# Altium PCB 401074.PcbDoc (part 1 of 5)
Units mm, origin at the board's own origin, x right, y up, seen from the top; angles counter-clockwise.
Board outline 70.15 x 35.15 mm, 6 copper layers (Top Layer, Mid-Layer1, Mid-Layer2, Mid-Layer3, Mid-Layer4, Bottom Layer), stack 1.549 mm thick; 239 components, 182 nets, 1034 pads, 1263 vias.
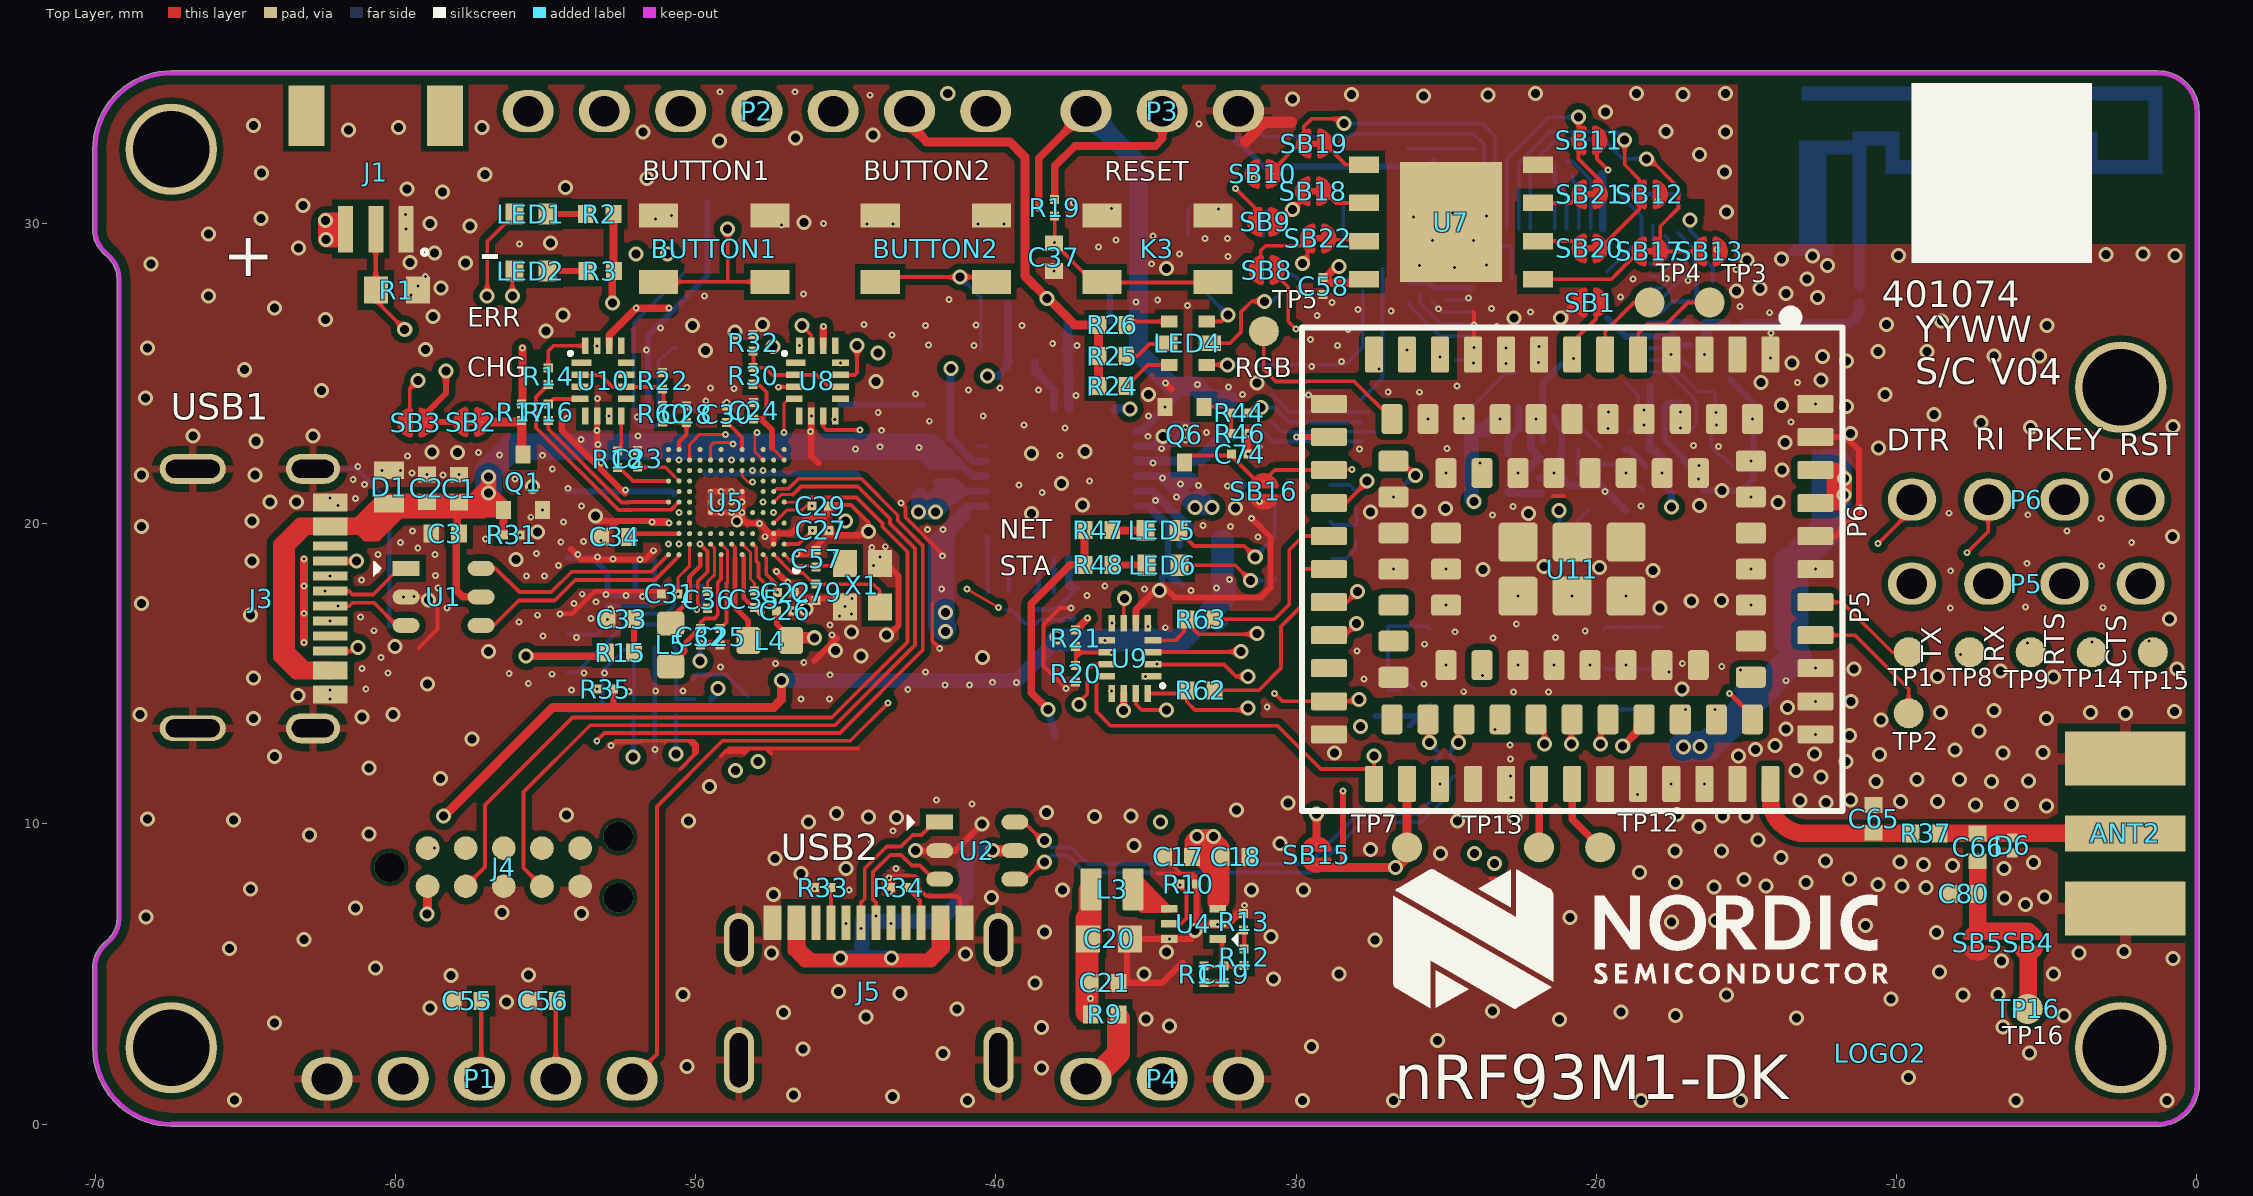
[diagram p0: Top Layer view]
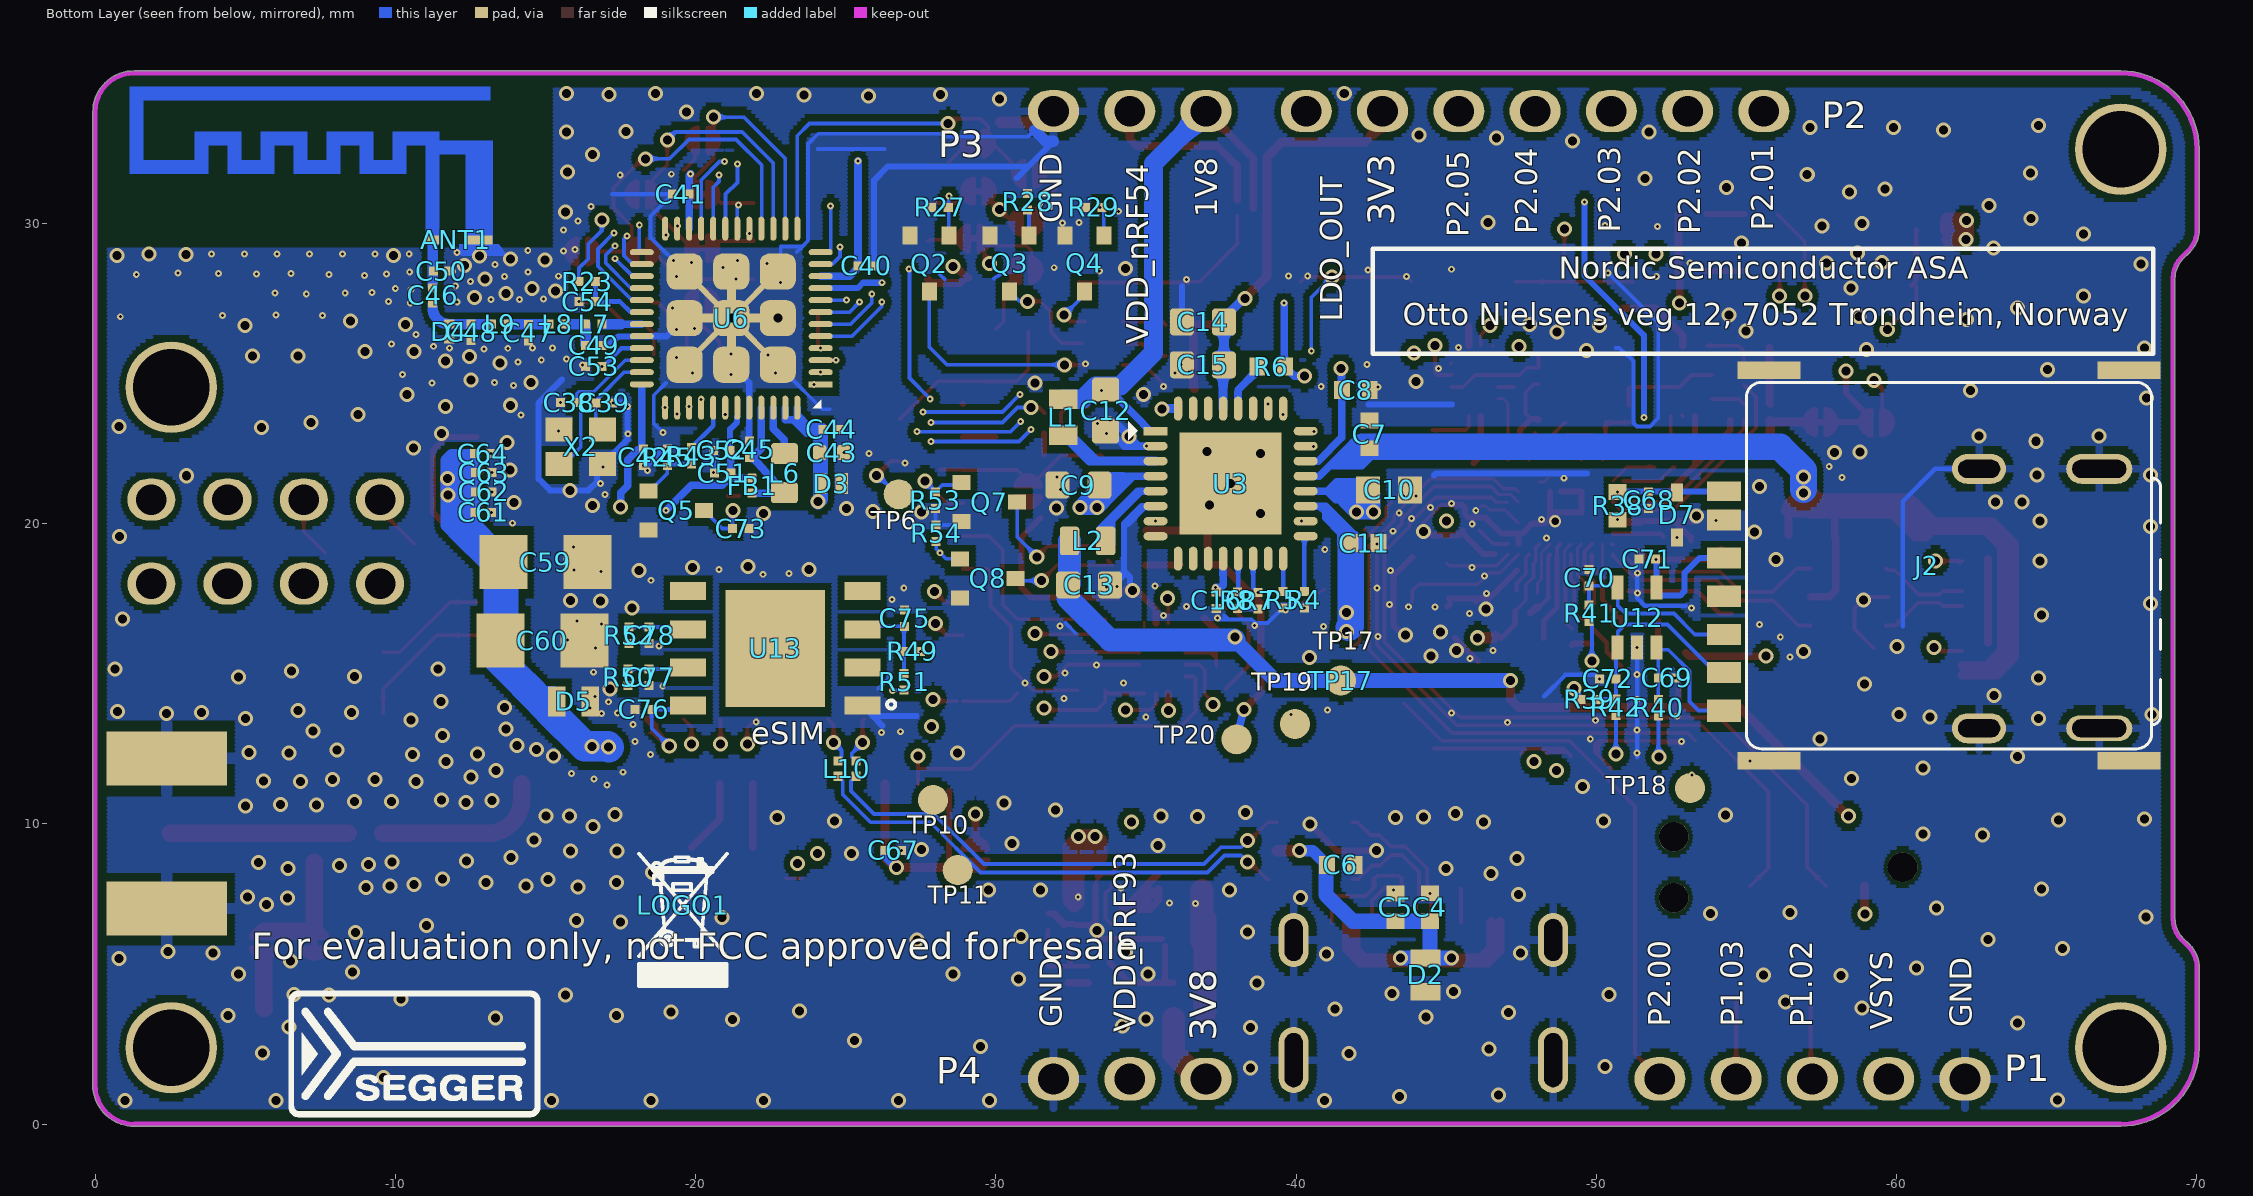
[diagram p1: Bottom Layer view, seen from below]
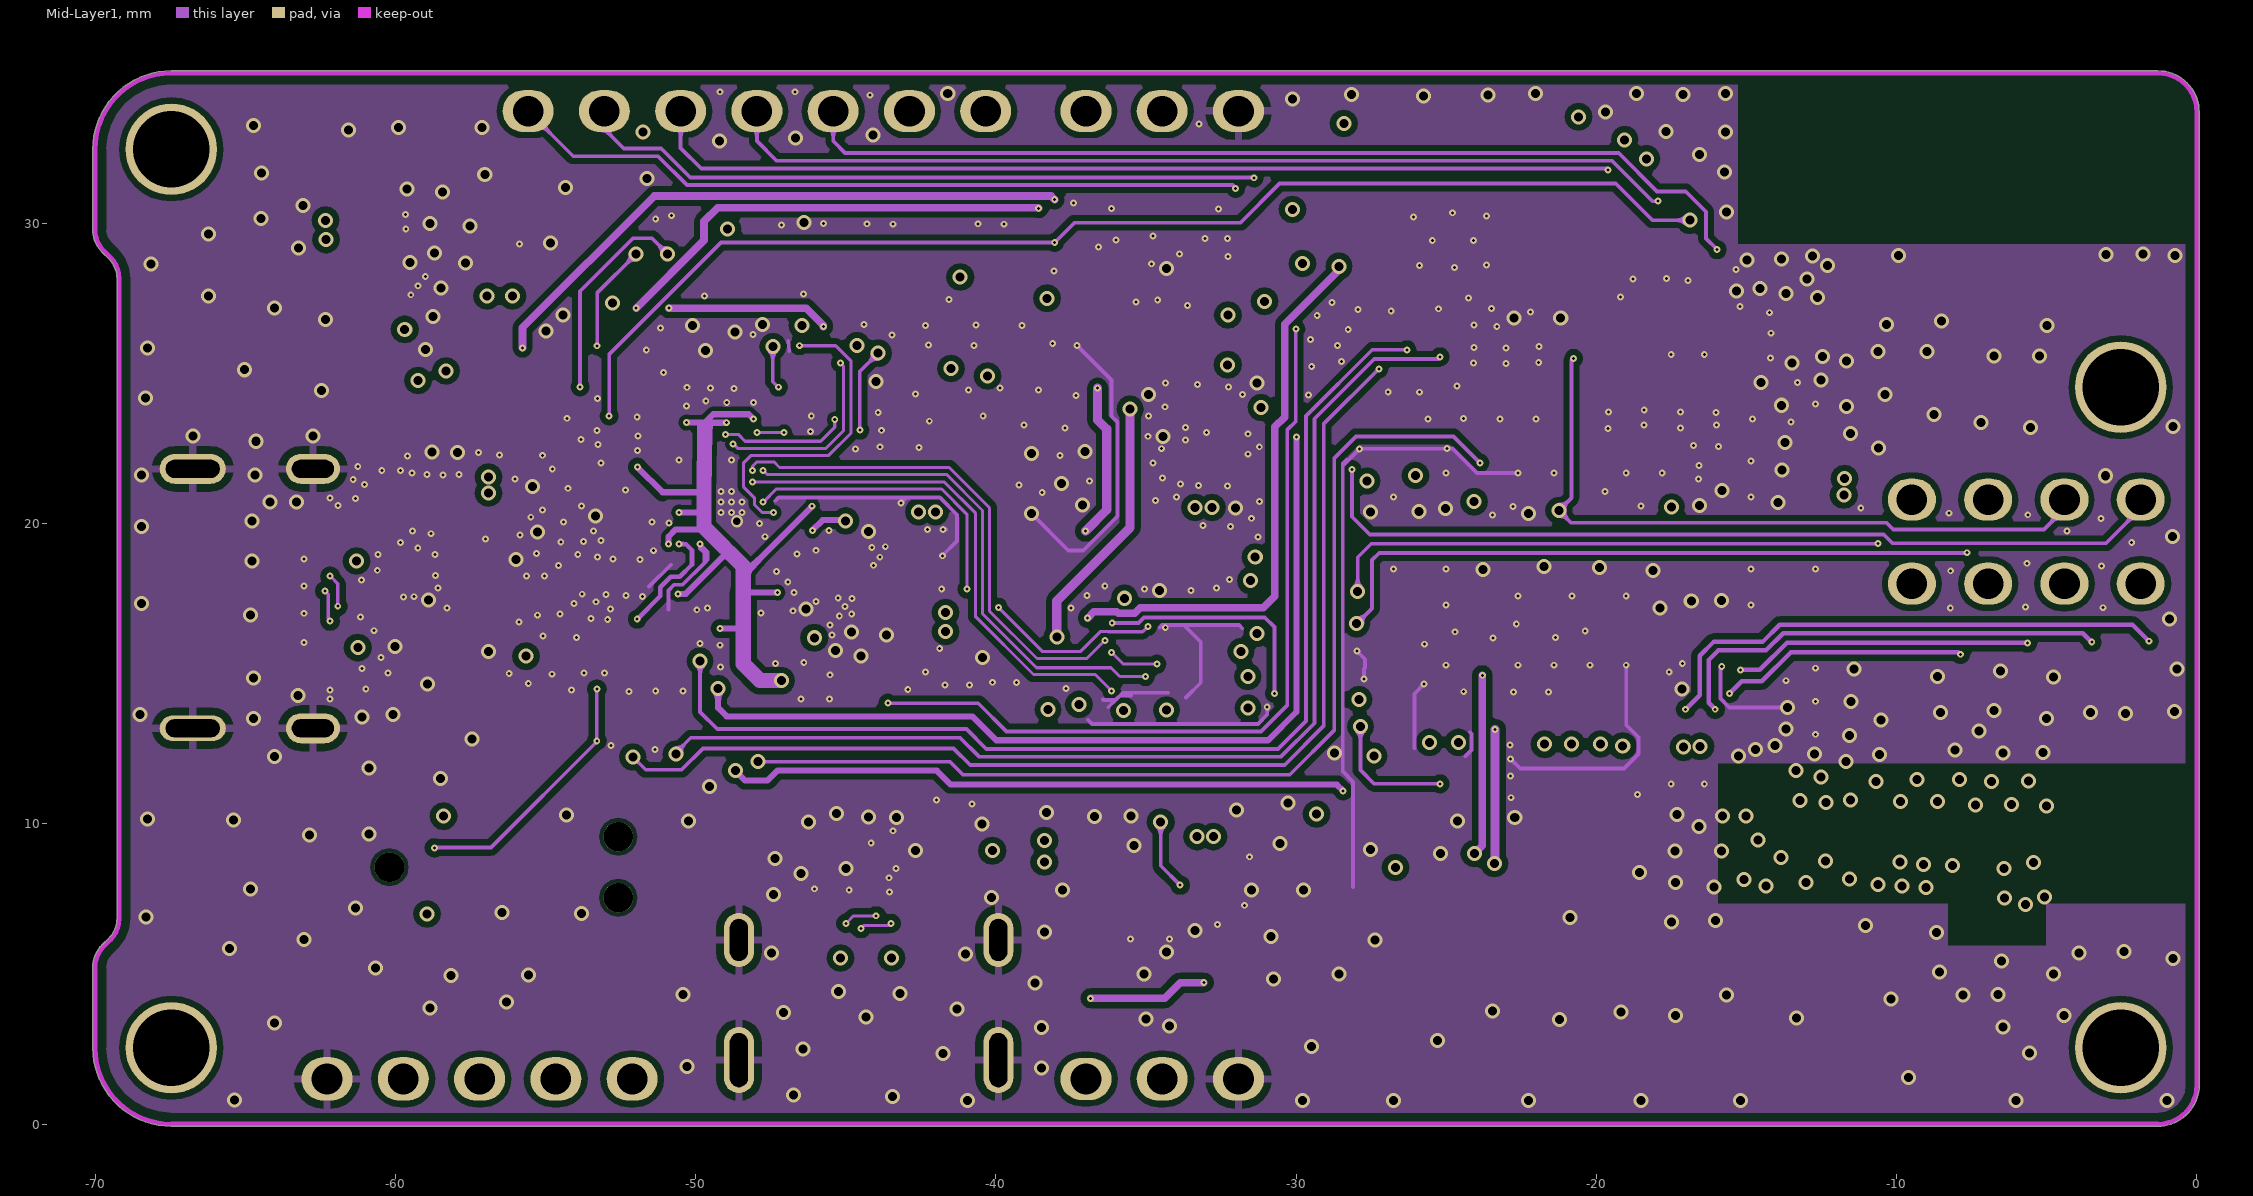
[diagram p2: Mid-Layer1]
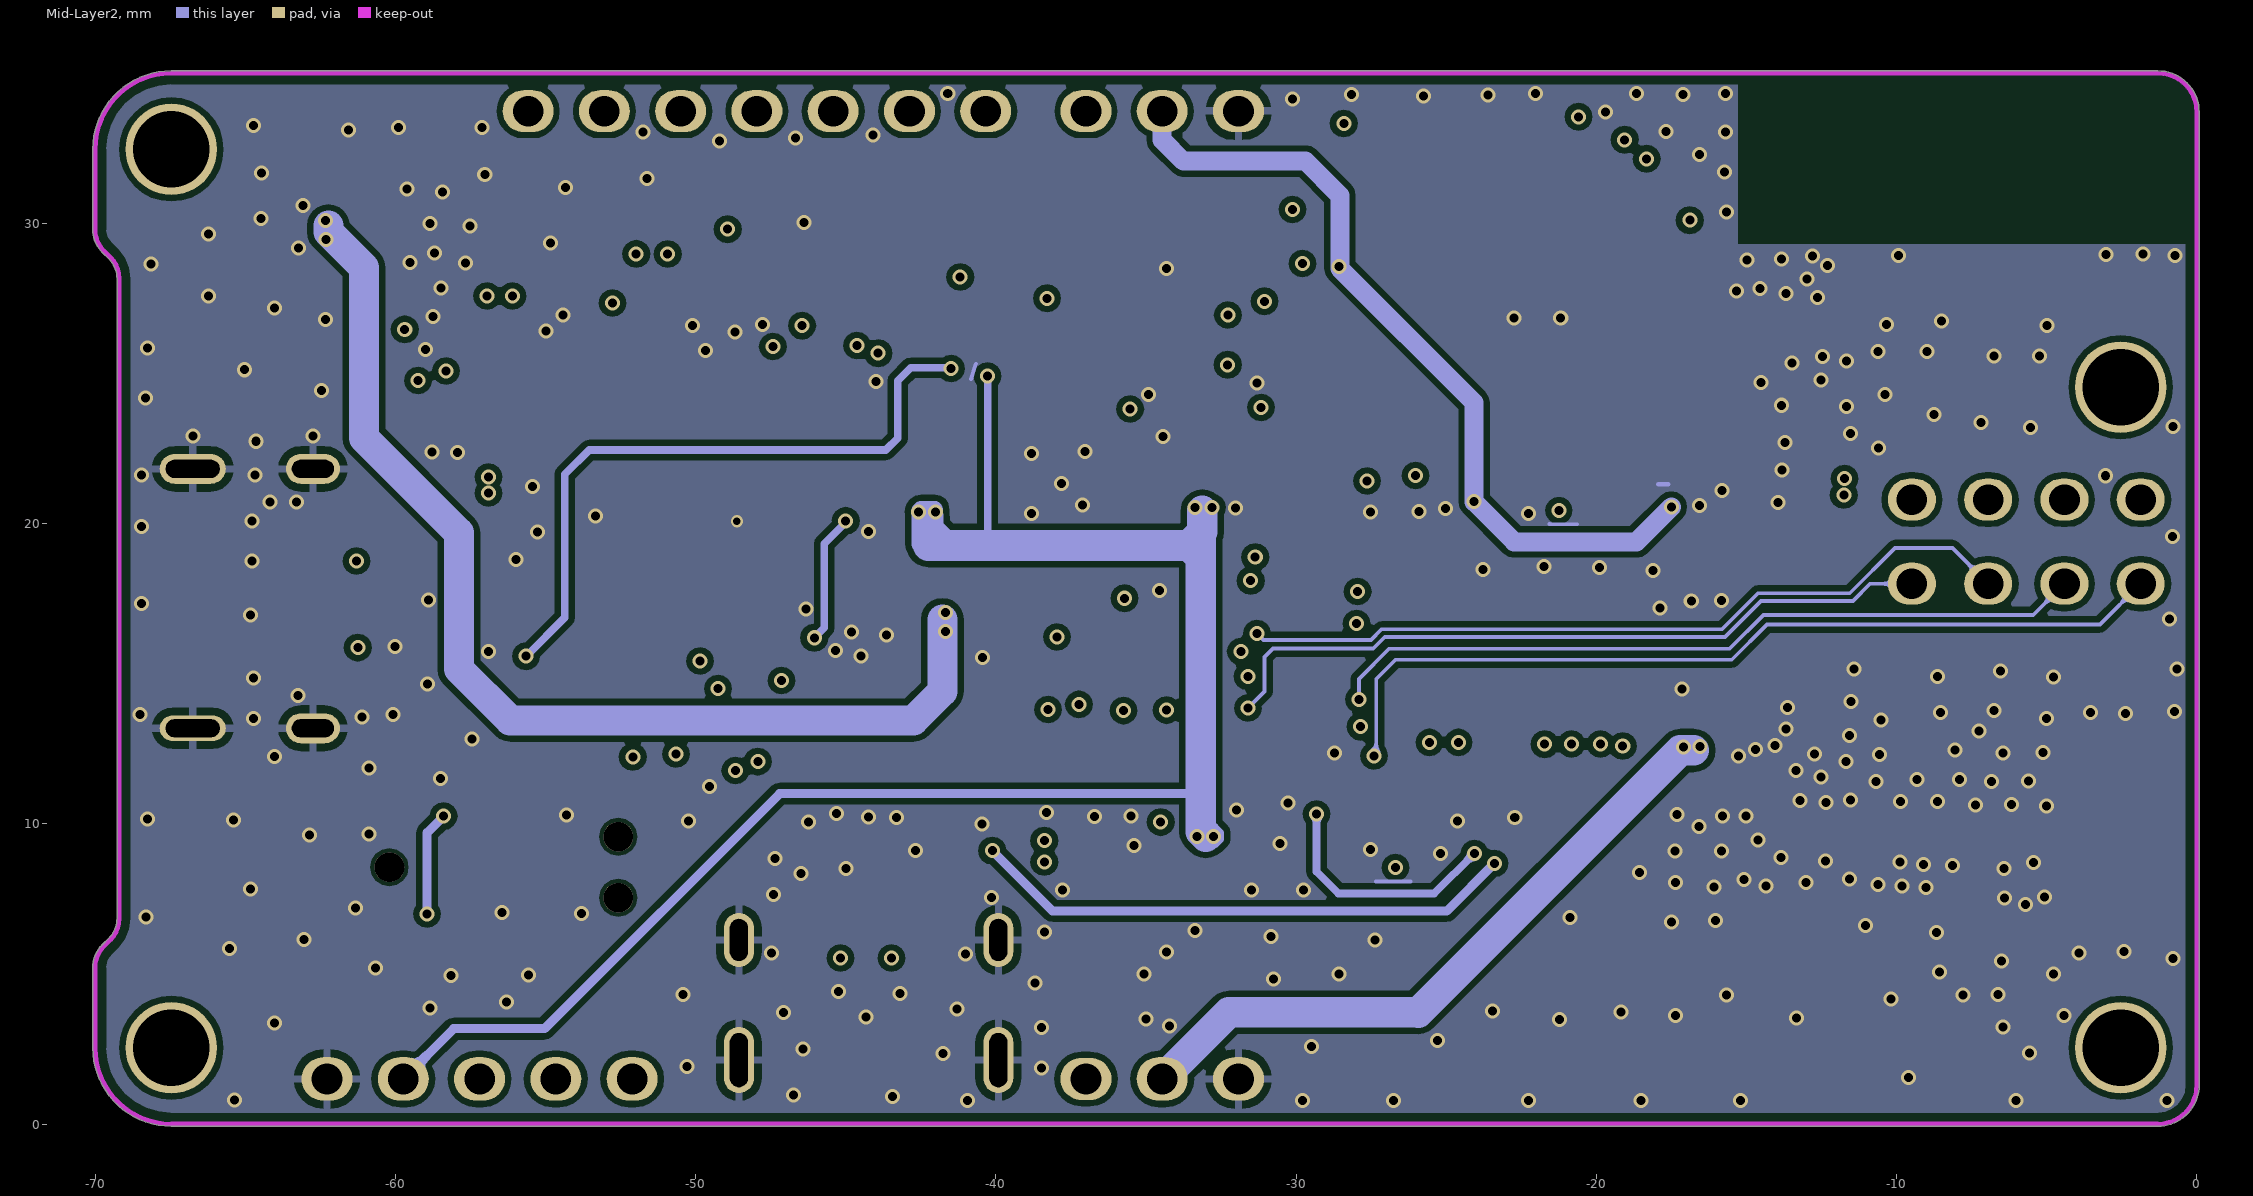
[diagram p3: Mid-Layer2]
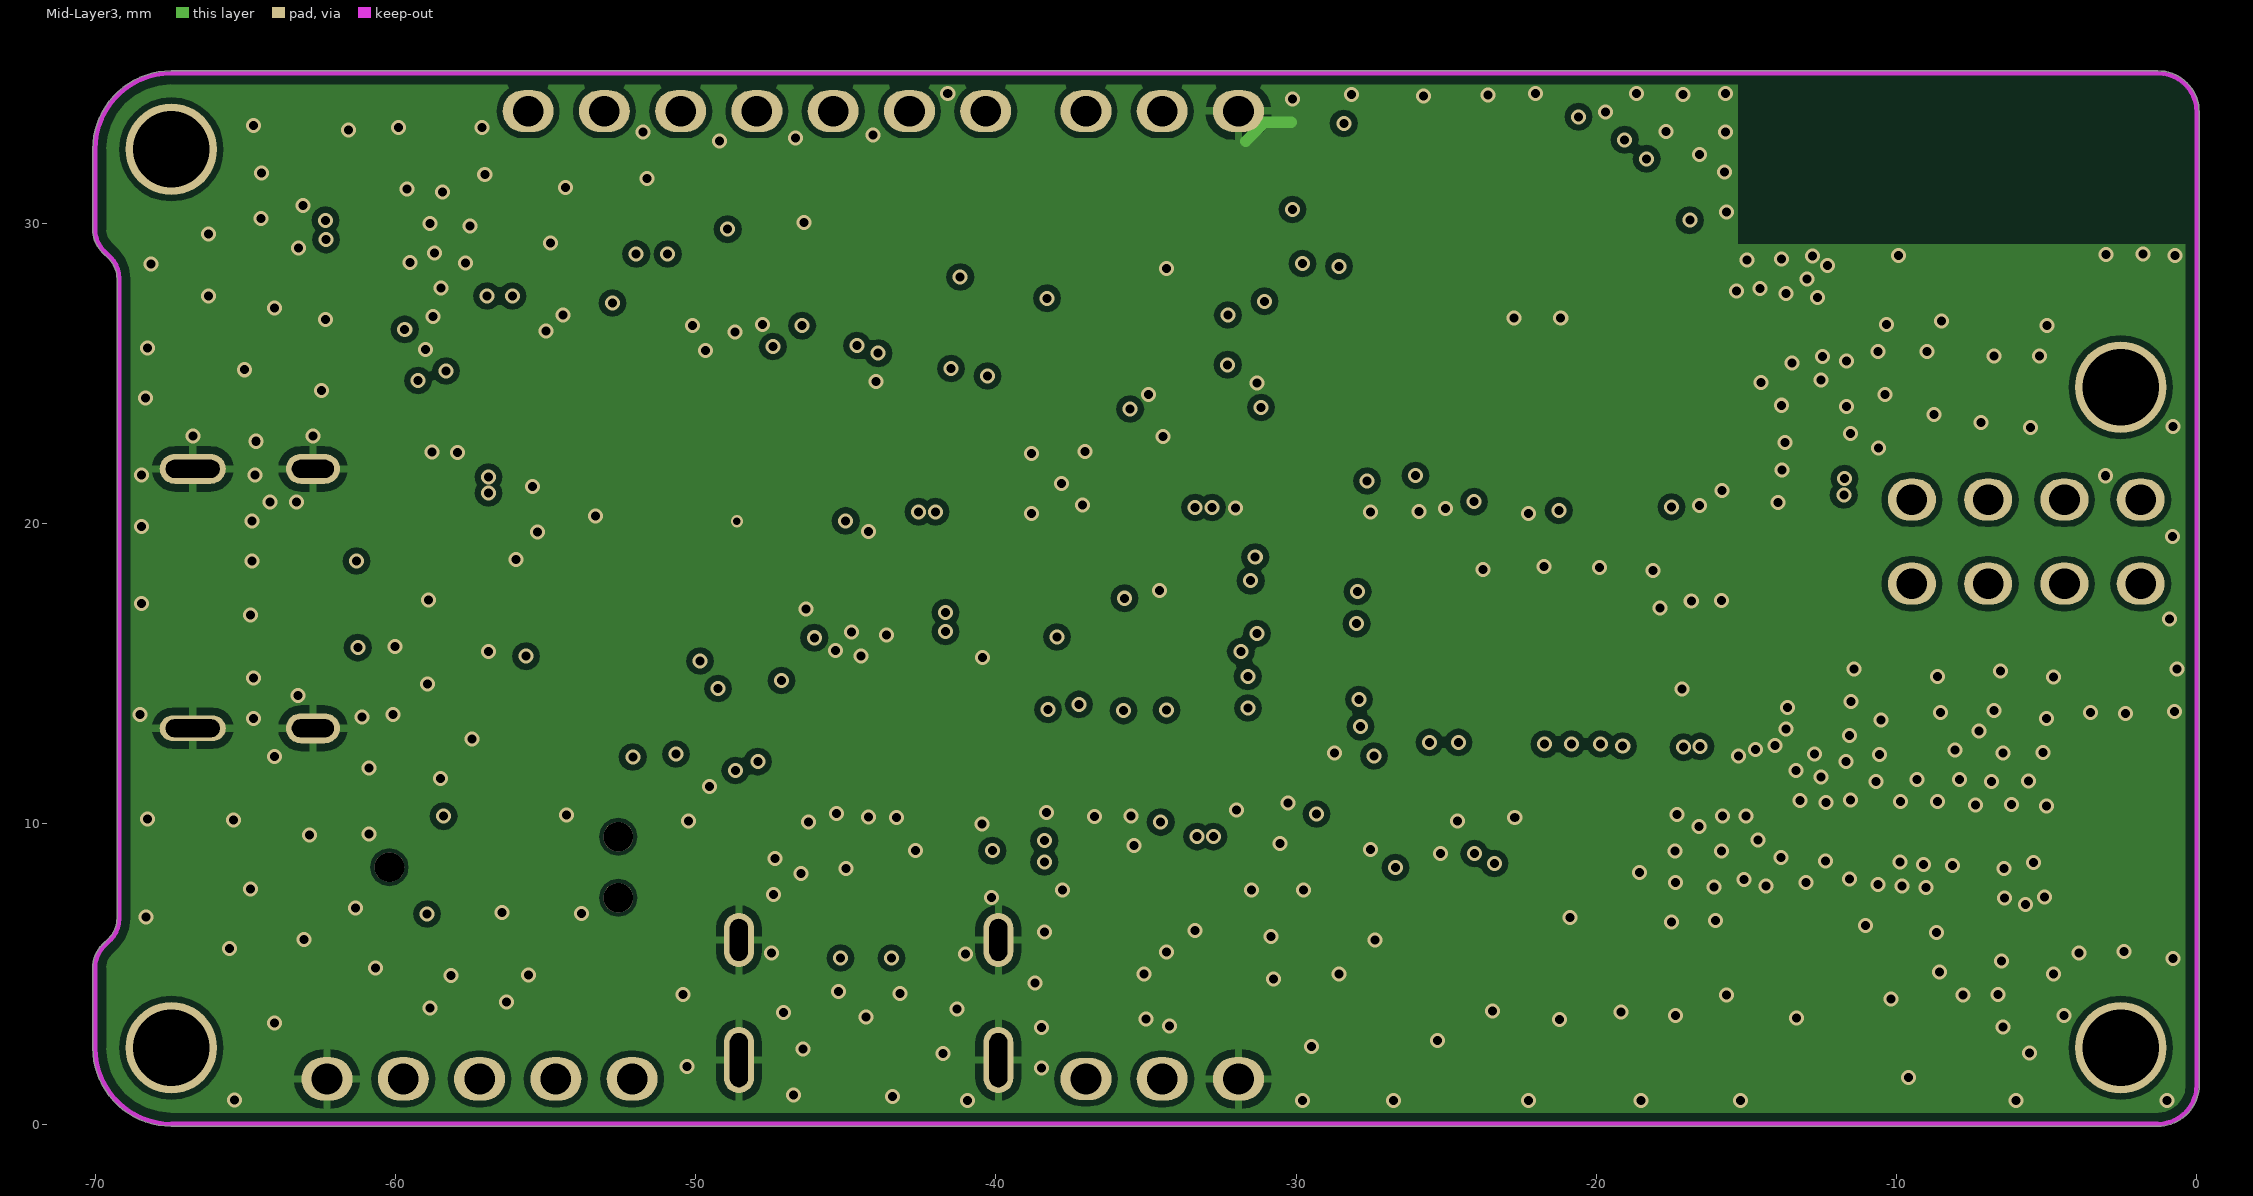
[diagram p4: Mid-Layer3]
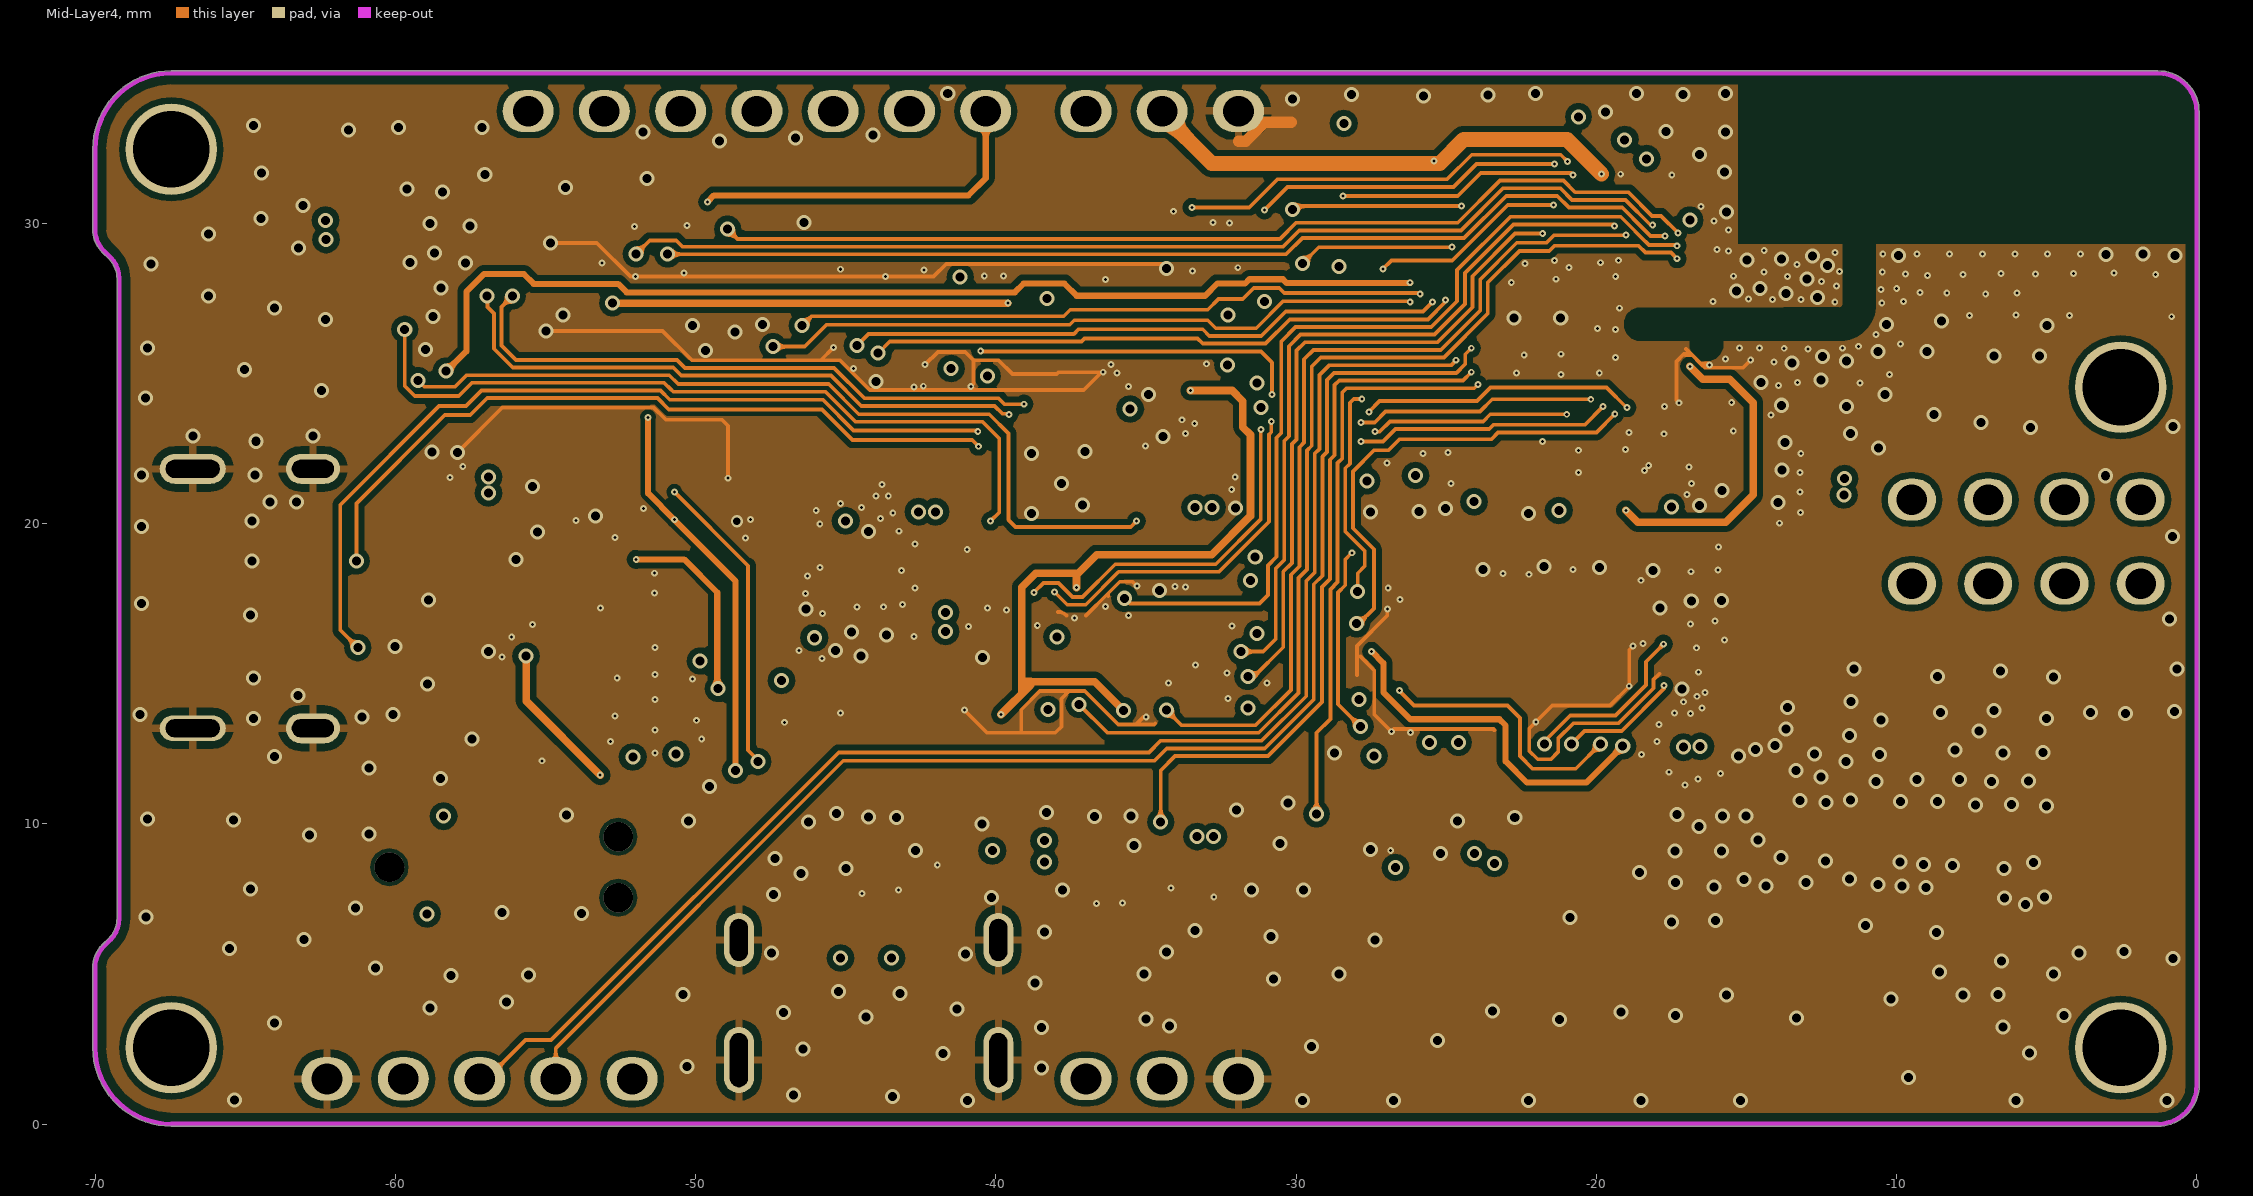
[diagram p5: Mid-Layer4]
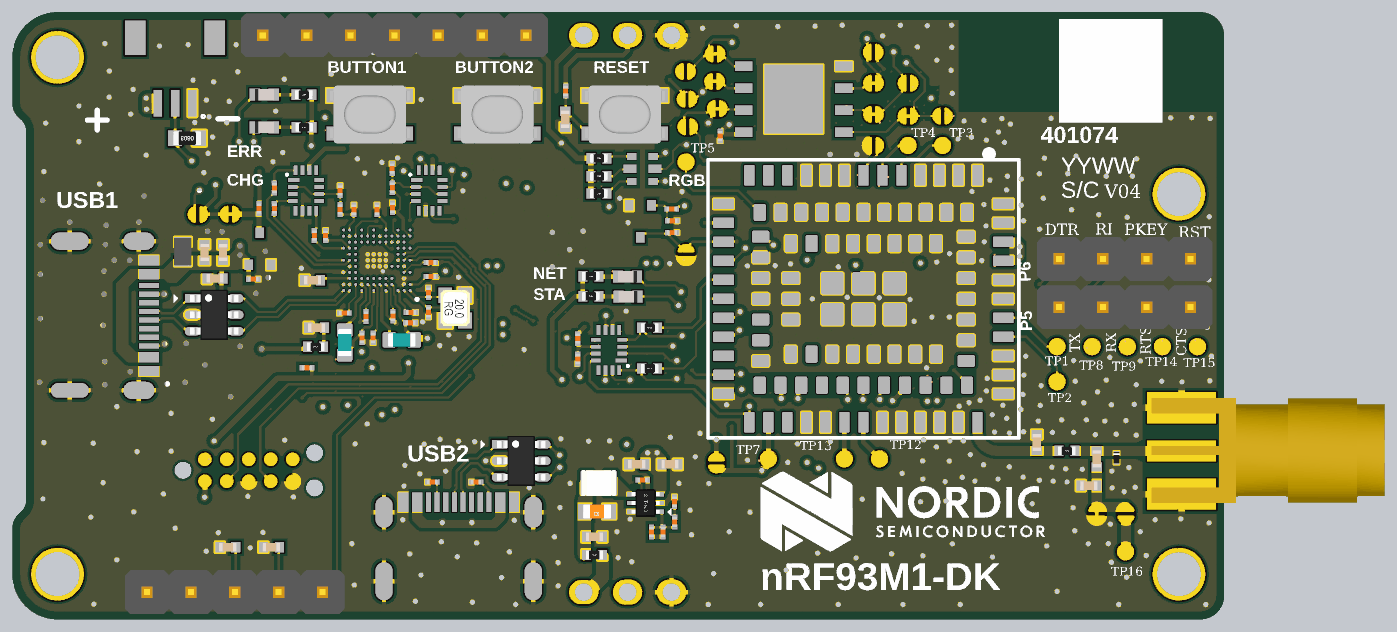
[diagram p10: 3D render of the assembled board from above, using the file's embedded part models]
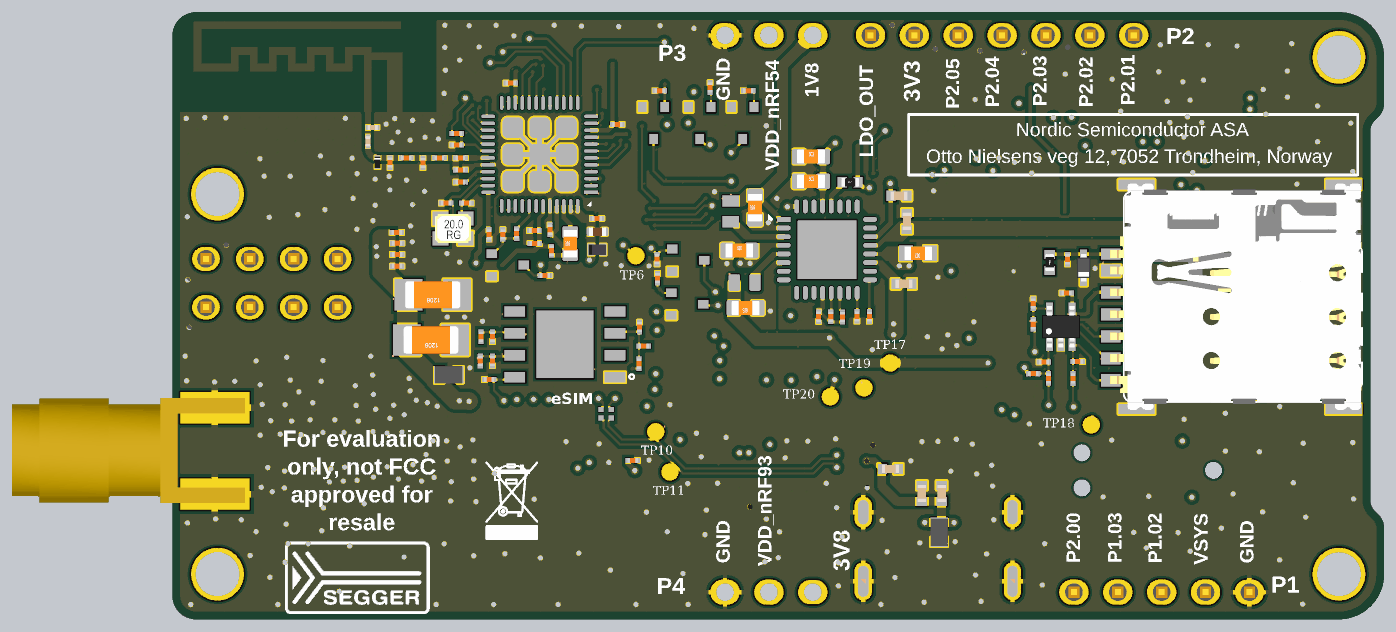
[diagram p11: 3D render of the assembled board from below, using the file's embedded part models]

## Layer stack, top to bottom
Top Solder: solder mask 0.0102, Solder Resist, Dk 3.5
Top Layer: signal copper 0.0356
Dielectric 1: prepreg 0.0762, FR-4, Dk 4.2
Mid-Layer1: signal copper 0.0356
Dielectric3: prepreg 0.127, FR-4, Dk 4.2
Mid-Layer2: signal copper 0.035
Dielectric 4: core 0.93, Dk 4.2
Mid-Layer3: signal copper 0.035
Dielectric 5: prepreg 0.127, Dk 4.2
Mid-Layer4: signal copper 0.036
Dielectric2: prepreg 0.0762, FR-4, Dk 3.6
Bottom Layer: signal copper 0.0356
Bottom Solder: solder mask 0.0102, Solder Resist, Dk 3.5

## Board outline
-70.075,2.54 -70.075,5.211 cw(c-69,5.211) -69.761,5.971 cw(c-69,5.211) -69.76,5.971 -69.541,6.19 ccw(c-70.195,6.844) -69.271,6.844 -69.271,28.156 ccw(c-70.195,28.156) -69.541,28.81 -69.76,29.029 cw(c-69,29.789) -70.075,29.789 -70.075,32.46 cw(c-67.46,32.46) -67.46,35.075 -1.3,35.075 cw(c-1.3,33.7) 0.075,33.701 cw(c0,33.7) 0.075,33.7 0.075,1.301 cw(c0,1.3) 0.075,1.3 cw(c-1.3,1.3) -1.3,-0.075 -67.46,-0.075 cw(c-67.46,2.54)

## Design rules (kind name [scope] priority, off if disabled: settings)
Clearance Clearance_room [WithinRoom('IMU5340 251105')] p1: gap=0.076 ignorepadtopadclearanceinfootprint=FALSE except(0.152: Arc-Fill Arc-Poly Arc-Region Track-Fill Track-Poly Track-Region SMDPad-Fill SMDPad-Poly SMDPad-Region THPad-Fill THPad-Poly THPad-Region Via-Fill Via-Poly Via-Region Fill-Fill Fill-Poly Fill-Region Poly-Poly Poly-Region Region-Region)
Clearance Clearance_keepout [IsKeepOut] p2: gap=0.3 ignorepadtopadclearanceinfootprint=FALSE
Clearance Clearance_via [IsVia vs IsVia] p3: gap=0.2 ignorepadtopadclearanceinfootprint=FALSE
Clearance Clearance_RF [InNetClass('ANT1')] p4: gap=0.178 ignorepadtopadclearanceinfootprint=FALSE except(0.125: Arc-Arc Arc-Track Track-Track Via-Fill Via-Poly Via-Region; 0.15: Arc-SMDPad Track-SMDPad)
Clearance [All] p5: gap=0.127 ignorepadtopadclearanceinfootprint=FALSE except(0.15: Arc-Fill Arc-Poly Arc-Region Track-Fill Track-Poly Track-Region; 0.2: SMDPad-Fill SMDPad-Poly SMDPad-Region THPad-Fill THPad-Poly THPad-Region Via-Fill Via-Poly Via-Region Fill-Fill Fill-Poly Fill-Region Poly-Poly Poly-Region Region-Region)
DiffPairsRouting [All] p1: maxlimit=0.254 minlimit=0.152 mostfreqgap=0.254 toplayer_minwidth=0.127 toplayer_maxwidth=0.381 toplayer_prefwidth=0.381 midlayer1_mingap=0.229 midlayer1_minwidth=0.089 midlayer1_maxwidth=0.381 midlayer1_prefwidth=0.381 midlayer2_mingap=0.254 midlayer2_minwidth=0.381 midlayer2_maxwidth=0.381 midlayer2_prefwidth=0.381 midlayer3_mingap=0.229 midlayer3_minwidth=0.089 midlayer3_maxwidth=0.381 midlayer3_prefwidth=0.381 midlayer4_mingap=0.254 midlayer4_minwidth=0.381 midlayer4_maxwidth=0.381 midlayer4_prefwidth=0.381 bottomlayer_minwidth=0.127 bottomlayer_maxwidth=0.381 bottomlayer_prefwidth=0.381 maxuncoupledlength=12.7
HoleToHoleClearance [All] p1: gap=0 allowstackedmicrovias=TRUE
MinimumSolderMaskSliver [All] p1: minsoldermaskwidth=0
PolygonConnect PolygonConnect_1 [InComponent('ANT2') or InComponent('CON1')] p1: connectstyle=Relief reliefconductorwidth=0.381 reliefentries=4 polygonreliefangle="90 Angle" airgapwidth=0.254
PolygonConnect [All] p2: thpad.connectstyle=Relief thpad.reliefconductorwidth=0.254 thpad.reliefentries=4 thpad.polygonreliefangle="90 Angle" thpad.airgapwidth=0.254 smdpad.connectstyle=Direct smdpad.reliefconductorwidth=0.254 smdpad.reliefentries=4 smdpad.polygonreliefangle="90 Angle" smdpad.airgapwidth=0.254 via.connectstyle=Direct via.reliefconductorwidth=0.254 via.reliefentries=4 via.polygonreliefangle="90 Angle" via.airgapwidth=0.254
RoomDefinition "IMU5340 251105" [InComponentClass('IMU5340 251105')] p1: confinementstyle=ConfineIn formatcopy=TRUE lockcomponents=FALSE outline -51.709,24.467 -45.178,24.467 -45.178,17.472 -51.709,17.472
RoutingVias [All] p1: holewidth=0.3 width=0.5 viastyle="Through Hole" minholewidth=0.1 minwidth=0.23 maxholewidth=0.3 maxwidth=0.5
ShortCircuit ShortCircuit_1 [InNet('ANT') vs InNet('GND')] p1: allowed=TRUE
ShortCircuit [All] p2: allowed=FALSE
SilkToSilkClearance [All] p1: silktosilkclearance=0
SilkToSolderMaskClearance [IsPad] p1: minsilkscreentomaskgap=0 clearancetoexposedcopper=TRUE
SolderMaskExpansion [All] p1: expansion=0.102 istentingtop=FALSE
SupplyNets "Schematic Supply Nets_2" [InNet('1V8')] p1: voltage=0.000
SupplyNets "Schematic Supply Nets_19" [InNet('3V3')] p2: voltage=0.000
SupplyNets "Schematic Supply Nets_18" [InNet('VDD_nRF93')] p3: voltage=0.000
SupplyNets "Schematic Supply Nets_17" [InNet('SIM1_VOUT')] p4: voltage=0.000
SupplyNets "Schematic Supply Nets_16" [InNet('nRF93_LDO_OUT')] p5: voltage=0.000
SupplyNets "Schematic Supply Nets_15" [InNet('3V8')] p6: voltage=0.000
SupplyNets "Schematic Supply Nets_14" [InNet('SIM2_VOUT')] p7: voltage=0.000
SupplyNets "Schematic Supply Nets_13" [InNet('VDD_nRF54')] p8: voltage=0.000
SupplyNets "Schematic Supply Nets_12" [InNet('VDD_DBGR')] p9: voltage=0.000
SupplyNets "Schematic Supply Nets_9" [InNet('VBUSOUT')] p10: voltage=0.000
SupplyNets "Schematic Supply Nets_7" [InNet('GND')] p11: voltage=0.000
SupplyNets "Schematic Supply Nets_5" [InNet('VBUS_PMIC')] p12: voltage=0.000
SupplyNets "Schematic Supply Nets_1" [InNet('VSYS')] p13: voltage=0.000
SupplyNets "Schematic Supply Nets" [InNet('VBAT_PMIC')] p14: voltage=0.000
UnRoutedNet [All] p1: checkbadconnections=TRUE
Width [All] p1: maxlimit=2.54 minlimit=0.076 preferedwidth=0.254
23 further rules are at their usual default settings.

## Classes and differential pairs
component class 01_PCA10232_DK: LOGO1 LOGO2
net class ANT1: ANT NetANT2_1 NetC46_1 NetC47_2 NetC49_2 NetC65_2 NetL7_1
component class 02_Power: C7 C8 C9 C10 C11 C12 C13 C14 C15 C16 C17 C18 C19 C20 C21 L1 L2 L3 LED1 LED2 P3 P4 R2 R3 R4 R5 R6 R7 R8 R9 R10 R11 R12 R13 TP17 TP18 TP19 TP20 U3 U4
component class 05_Port_Switch: R20 R21 R22 R30 R32 R60 U8 U9 U10
component class 06_IMU_nRF5340: C22 C23 C24 C25 C26 C27 C28 C29 C30 C31 C32 C33 C34 C35 C36 C57 C79 L4 L5 R14 R15 R16 R18 R35 U5 X1
component class 03_Host_nRF54L15: ANT1 BUTTON1 BUTTON2 C37 C38 C39 C40 C41 C42 C43 C44 C45 C46 C47 C48 C49 C50 C51 C52 C53 C54 C58 D3 D4 FB1 K3 L6 L7 L8 L9 LED4 Q1 Q2 Q3 Q4 R17 R19 R23 R24 R25 R26 R27 R28 R29 R31 SB2 SB3 SB8 SB9 SB10 SB11 SB12 SB13 SB17 SB18 SB19 SB20 SB21 SB22 U6 U7 X2
component class 07_Connectors: C1 C2 C3 C4 C5 C6 C55 C56 D1 D2 J1 J3 J4 J5 P1 P2 P5 P6 R1 R33 R34 U1 U2
component class 04_nRF93M1: ANT2 C59 C60 C61 C62 C63 C64 C65 C66 C67 C68 C69 C70 C71 C72 C73 C74 C75 C76 C77 C78 C80 D5 D6 D7 J2 L10 LED5 LED6 Q5 Q6 Q7 Q8 R37 R38 R39 R40 R41 R42 R43 R44 R45 R46 R47 R48 R49 R50 R51 R52 R53 R54 R62 R63 SB1 SB4 SB5 SB15 SB16 TP1 TP2 TP3 TP4 TP5 TP6 TP7 TP8 TP9 TP10 TP11 TP12 TP13 TP14 TP15 TP16 U11 U12 U13
differential pair USB2: +USB2_P -USB2_N
differential pair D: +D_P -D_N
differential pair D2: +D2_P -D2_N
differential pair D1: +D1_P -D1_N

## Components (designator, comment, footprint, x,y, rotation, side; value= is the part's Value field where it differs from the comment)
ANT1 "ANT-2P-2" ANT_PCB -11.236,29.444 r180 bottom locked
ANT2 "SMA" SMA-SMD -2.385,9.676 r270 top locked
BUTTON1 "SW PB" SW-4.2X3.35-4P-S -49.379,29.15 r180 top locked
BUTTON2 "SW PB" SW-4.2X3.35-4P-S -42,29.15 r180 top locked
C1 "100nF" 0402C_0.4D -57.877,21.163 r270 top
C2 "4.7µF" 0402C_0.4D -58.949,21.171 r270 top
C3 "100nF" 0402C_0.4D -58.344,19.659 r0 top
C4 "100nF" 0402C_0.4D -44.458,7.219 r270 bottom
C5 "4.7µF" 0402C_0.4D -43.315,7.217 r270 bottom
C6 "100nF" 0402C_0.4D -41.488,8.632 r0 bottom
C7 "1µF" 0402C_0.4D -42.449,22.968 r270 bottom
C8 "1µF" 0402C_0.4D -41.99,24.445 r0 bottom
C9 "10µF" 0603C_0.6D#1 -32.749,21.278 r180 bottom
C10 "10µF" 0603C_0.6D#2 -43.096,21.122 r0 bottom
C11 "2.2µF" 0402C_0.4D -42.277,19.345 r0 bottom
C12 "10µF" 0603C_0.6D#1 -33.654,23.761 r90 bottom
C13 "10µF" 0603C_0.6D#1 -33.105,17.952 r0 bottom
C14 "10µF" 0603C_0.6D#1 -36.894,26.714 r180 bottom
C15 "10µF" 0603C_0.6D#1 -36.894,25.284 r180 bottom
C16 "100nF" 0201_0.25D -37.34,17.444 r90 bottom
C17 "4.7µF" 0402C_0.4D -33.929,8.899 r0 top
C18 "1µF" 0402C_0.4D -32.012,8.899 r180 top
C19 "20pF" 0201_0.25D -32.41,4.983 r270 top
C20 "22µF" 0603C_0.6D#2 -36.227,6.167 r180 top
C21 "10µF" 0402C_0.4D -36.38,4.703 r180 top
C22 "100nF" 0201_0.25D -47.002,17.699 r180 top
C23 "100nF" 0201_0.25D -51.937,22.151 r270 top
C24 "1µF" 0201_0.25D -48.071,23.754 r270 top
C25 "1µF" 0201_0.25D -49.188,16.221 r90 top
C26 "1µF" 0201_0.25D -47.029,17.093 r180 top
C27 "2.2nF" 0201_0.25D -45.837,19.768 r180 top
C28 "100nF" 0201_0.25D -50.303,23.636 r270 top
C29 "100nF" 0201_0.25D -45.847,20.575 r180 top
C30 "100nF" 0201_0.25D -48.969,23.631 r270 top
C31 "1µF" 0201_0.25D -50.864,17.655 r0 top
C32 "1µF" 0201_0.25D -49.836,16.221 r90 top
C33 "4.7µF" 0402C_0.4D -52.466,16.814 r0 top
C34 "4.7µF" 0402C_0.4D -52.692,19.553 r0 top
C35 "100nF" 0201_0.25D -48.045,17.479 r90 top
C36 "1µF" 0201_0.25D -49.602,17.452 r90 top
C37 "100pF" 0402C_0.4D -38.066,28.874 r90 top
C38 "N.C." 0201_0.25D -15.767,24.023 r180 bottom
C39 "N.C." 0201_0.25D -16.951,24.021 r180 bottom
C40 "100nF" 0201_0.25D -25.685,28.58 r0 bottom
C41 "100nF" 0201_0.25D -19.511,30.969 r180 bottom
C42 "100nF" 0201_0.25D -18.257,22.203 r90 bottom
C43 "10µF" 0402C_0.4D-NB -24.538,22.359 r0 bottom
C44 "100nF" 0201_0.25D -24.51,23.138 r0 bottom
C45 "2.2µF" 0201_0.25D -21.787,22.478 r270 bottom
C46 "220pF" 0201C_0.2D(NB) -11.244,27.595 r90 bottom
C47 "2pF" 0201_0.25D -14.43,26.349 r90 bottom
C48 "0.3pF" 0201_0.25D -12.525,26.364 r90 bottom
C49 "1.5pF" 0201_0.25D -16.61,25.935 r0 bottom
C50 "220pF" 0201C_0.2D(NB) -11.52,28.405 r0 bottom
C51 "2.2µF" 0201_0.25D -20.9,21.676 r180 bottom
C52 "10nF" 0201_0.25D -20.875,22.439 r180 bottom
C53 "10nF" 0201_0.25D -16.61,25.235 r180 bottom
C54 "3.9pF" 0201_0.25D -16.391,27.393 r180 bottom
C55 "100pF" 0402C_0.4D -57.603,4.1 r0 top
C56 "100pF" 0402C_0.4D -55.083,4.1 r180 top
C57 "N.C." 0201_0.25D -45.987,18.833 r270 top
C58 "100nF" 0201_0.25D -29.1,27.91 r90 top
C59 "100µF" 1206C_1.2D -15,18.715 r0 bottom
C60 "100µF" 1206C_1.2D -14.9,16.099 r0 bottom
C61 "100nF" 0201_0.25D -12.933,20.37 r0 bottom
C62 "100pF" 0201_0.25D -12.941,21.052 r0 bottom
C63 "33pF" 0201_0.25D -12.94,21.698 r0 bottom
C64 "8.2pF" 0201_0.25D -12.918,22.328 r0 bottom
C65 "N.C." 0402C_0.4D -10.767,10.159 r270 top
C66 "N.C." 0402C_0.4D -7.301,9.214 r90 top
C67 "4.7µF" 0201_0.25D -26.575,9.113 r0 bottom
C68 "33pF" 0201_0.25D -51.74,20.77 r270 bottom
C69 "33pF" 0201_0.25D -52.336,14.858 r0 bottom
C70 "33pF" 0201_0.25D -49.759,18.201 r270 bottom
C71 "100nF" 0201_0.25D -51.694,18.817 r180 bottom
C72 "33pF" 0201_0.25D -50.375,14.823 r180 bottom
C73 "N.C." 0201_0.25D -21.502,19.829 r0 bottom
C74 "N.C." 0201_0.25D -31.883,22.307 r180 top
C75 "33pF" 0201_0.25D -26.963,16.851 r270 bottom
C76 "100nF" 0201_0.25D -18.264,13.806 r180 bottom
C77 "33pF" 0201_0.25D -18.453,14.879 r90 bottom
C78 "33pF" 0201_0.25D -18.453,16.279 r90 bottom
C79 "N.C." 0201_0.25D -45.987,17.704 r270 top
C80 "N.C." 0402C_0.4D -7.76,7.666 r180 top
D1 "WS6.3DPX" UDFN2(1610) -60.206,21.214 r90 top
D2 "WS6.3DPX" UDFN2(1610) -44.314,4.968 r270 bottom
D3 "1409000820" DFN1006 -24.517,21.33 r180 bottom
D4 "1409000820" D0201-NP -11.796,26.387 r270 bottom
D5 "DIODE-TVS" UDFN2(1610) -15.934,14.079 r180 bottom
D6 "1409000820" D0201-NP -6.155,9.28 r270 top
D7 "TVS/5V" SOD-523-NP -52.68,20.283 r90 bottom
FB1 "240R/0.35A/380mΩ" 0201L_0.2D(NB) -21.881,21.26 r270 bottom
J1 "WF-1F100A3P   1.0mm 3p" CON1 -60.653,31.855 r180 top locked
J2 "MUP-C7801-22" SIM-MUP-C7801 -61,18.597 r90 bottom locked
J3 "USB-TYPE C-16" USB-TYPEC-MUP-U20402-1#1 -65.597,17.5 r270 top locked
J4 "TC2050-IDC" TC2050-IDC-NLFP -56.388,8.552 r0 top locked
J5 "USB-TYPE C-16" USB-TYPEC-MUP-U20402-1#2 -44.238,3.279 r0 top locked
K3 "SW PB" SW-4.2X3.35-4P-S -34.622,29.15 r180 top locked
L1 "2.2µH" SKFB160808-2R2M#1 -32.241,23.539 r90 bottom
L2 "2.2µH" SKFB160808-2R2M#2 -33.054,19.421 r0 bottom
L3 "2.2µH" 0805L_0.7D-NB -36.13,7.817 r180 top
L4 "N.C." 0603L_0.6D -47.53,16.1 r180 top
L5 "N.C." 0603L_0.6D -50.828,15.954 r90 top
L6 "4.7µH" 0603C_0.6D(RF) -22.956,21.676 r90 bottom
L7 "2.7nH" 0201_0.25D -16.61,26.637 r0 bottom
L8 "3.5nH" 0201_0.25D -15.395,26.637 r0 bottom
L9 "3.5nH" 0201_0.25D -13.469,26.637 r0 bottom
L10 "DLM0NSN900HY2D" L-0.85X0.65 -25.037,11.832 r270 bottom
LED1 "RED/25mA" D0402 -55.484,30.3 r0 top
LED2 "GREEN/25mA" D0402 -55.484,28.409 r0 top
LED4 "LED RGB" D1616-RGB -33.603,26.003 r180 top
LED5 "Blue/25mA" D0402 -34.464,19.767 r180 top
LED6 "GREEN/25mA" D0402 -34.436,18.609 r180 top
LOGO1 "WEE Symbol" WEEE_3x4.5mm -19.577,7.29 r0 bottom locked
LOGO2 "Segger Logo S" logo -10.546,2.355 r180 top
P1 "SPI 5-M" "SIP 2.54_5_S" -62.275,1.5 r90 top locked
P2 "SPI 7-M" "SIP 2.54_7_S" -55.578,33.735 r90 top locked
P3 "2.54mm/1*3PIN" "SIP 2.54_3_S"#1 -37,33.735 r90 top locked
P4 "2.54mm/1*3PIN" "SIP 2.54_3_S"#2 -37,1.5 r90 top
P5 "SPI 4-M" "SIP 2.54_4_S" -9.491,17.994 r90 top locked
P6 "SPI 4-M" "SIP 2.54_4_S" -9.491,20.794 r90 top locked
Q1 "WNM2021-3/TR" SOT-323-3G -55.749,21.374 r270 top
Q2 "WNM2021-3/TR" SOT-323-3G -27.783,28.659 r90 bottom
Q3 "WNM2021-3/TR" SOT-323-3G -30.455,28.659 r90 bottom
Q4 "WNM2021-3/TR" SOT-323-3G -32.945,28.659 r90 bottom
Q5 "MMST3904-TP" SOT-323-3A -19.349,20.44 r0 bottom
Q6 "MMST3904-TP" SOT-323-3A -33.722,22.962 r90 top
Q7 "WNM2021-3/TR" SOT-323-3G -29.787,20.712 r0 bottom
Q8 "WNM2021-3/TR" SOT-323-3G -29.736,18.175 r0 bottom
R1 "N.C." 0603R_0.6D -59.953,27.776 r180 top
R2 "470Ω" 0402R_0.4D -53.199,30.3 r180 top
R3 "470Ω" 0402R_0.4D -53.18,28.402 r180 top
R4 "47kΩ" 0201_0.25D -40.277,17.461 r90 bottom
R5 "4.7kΩ" 0201_0.25D -39.557,17.464 r90 bottom
R6 "0Ω" 0402R_0.4D -39.165,25.225 r180 bottom
R7 "10KΩ" 0201_0.25D -38.727,17.433 r270 bottom
R8 "10KΩ" 0201_0.25D -38.041,17.437 r90 bottom
R9 "0Ω" 0402R_0.4D -36.38,3.653 r0 top
R10 "51kΩ" 0201_0.25D -33.589,7.988 r180 top
R11 "100kΩ" 0201_0.25D -33.076,4.983 r270 top
R12 "18KΩ" 0201_0.25D -31.732,5.556 r270 top
R13 "750Ω" 0201_0.25D -31.75,6.736 r270 top
R14 "150Ω" 0201_0.25D -54.908,24.897 r90 top
R15 "2.2Ω" 0402R_0.4D -52.515,15.7 r180 top
R16 "150Ω" 0201_0.25D -54.908,23.706 r90 top
R17 "1MΩ" 0201_0.25D -55.792,23.705 r90 top
R18 "150Ω" 0201_0.25D -52.597,22.143 r90 top
R19 "100KΩ" 0201_0.25D -38.041,30.513 r90 top
R20 "100KΩ" 0201_0.25D -37.342,14.997 r90 top
R21 "N.C." 0201_0.25D -37.342,16.176 r270 top
R22 "100KΩ" 0201_0.25D -51.098,24.752 r90 top
R23 "1KΩ" 0201_0.25D -16.391,28.053 r0 bottom
R24 "330Ω" 0402R_0.4D -36.122,24.574 r180 top
R25 "330Ω" 0402R_0.4D -36.122,25.574 r180 top
R26 "330Ω" 0402R_0.4D -36.122,26.613 r180 top
R27 "1MΩ" 0201_0.25D -28.139,30.525 r0 bottom
R28 "1MΩ" 0201_0.25D -31.056,30.716 r90 bottom
R29 "1MΩ" 0201_0.25D -33.258,30.525 r0 bottom
R30 "10KΩ" 0201_0.25D -48.082,24.912 r270 top
R31 "1MΩ" 0201_0.25D -56.124,19.618 r0 top
R32 "100KΩ" 0201_0.25D -48.087,26.021 r90 top
R33 "5.1kΩ" 0201_0.25D -45.763,7.873 r0 top
R34 "5.1kΩ" 0201_0.25D -43.23,7.873 r0 top
R35 "150Ω" 0201_0.25D -53.016,14.487 r180 top
R37 "0Ω" 0402R_0.4D -9.034,9.676 r0 top
R38 "N.C." 0402R_0.4D -50.709,20.588 r90 bottom
R39 "N.C." 0201_0.25D -49.763,14.146 r0 bottom
R40 "22Ω" 0201_0.25D -52.066,13.871 r90 bottom
R41 "22Ω" 0201_0.25D -49.759,17.011 r90 bottom
R42 "22Ω" 0201_0.25D -50.65,13.875 r270 bottom
R43 "4.7KΩ" 0201_0.25D -19.857,22.255 r270 bottom value=4.7kΩ
R44 "4.7KΩ" 0201_0.25D -31.898,23.682 r180 top value=4.7kΩ
R45 "47KΩ" 0201_0.25D -19.055,22.211 r90 bottom value=47kΩ
R46 "47KΩ" 0201_0.25D -31.875,22.996 r0 top value=47kΩ
R47 "330Ω" 0402R_0.4D -36.584,19.777 r180 top
R48 "330Ω" 0402R_0.4D -36.585,18.621 r180 top
R49 "N.C." 0201_0.25D -27.213,15.74 r180 bottom
R50 "22Ω" 0201_0.25D -17.749,14.879 r270 bottom
R51 "22Ω" 0201_0.25D -26.942,14.722 r90 bottom
R52 "22Ω" 0201_0.25D -17.789,16.279 r270 bottom
R53 "1MΩ" 0201_0.25D -27.985,20.777 r270 bottom
R54 "1MΩ" 0201_0.25D -28.012,19.677 r90 bottom
R60 "10KΩ" 0201_0.25D -51.098,23.654 r270 top
R62 "0Ω" 0402R_0.4D -33.179,14.444 r0 top
R63 "0Ω" 0402R_0.4D -33.179,16.809 r0 top
SB1 "Solderbridge" Solderbridge_NO_Shorted#1 -20.205,27.36 r0 top
SB2 "Solderbridge_Shorted" Solderbridge_Shorted#1 -57.468,23.379 r180 top net-tie
SB3 "Solderbridge" Solderbridge_NO_Shorted#1 -59.329,23.361 r180 top
SB4 "Solderbridge" Solderbridge_NO_Shorted#2 -5.613,6.036 r90 top
SB5 "Solderbridge_Shorted" Solderbridge_Shorted#2 -7.301,6.036 r90 top net-tie
SB8 "Solderbridge" Solderbridge_NO_Shorted#1 -30.976,28.442 r180 top
SB9 "Solderbridge" Solderbridge_NO_Shorted#1 -31.02,30.043 r0 top
SB10 "Solderbridge" Solderbridge_NO_Shorted#1 -31.108,31.643 r0 top
SB11 "Solderbridge" Solderbridge_NO_Shorted#1 -20.241,32.76 r180 top
SB12 "Solderbridge" Solderbridge_NO_Shorted#1 -18.225,30.96 r180 top
SB13 "Solderbridge" Solderbridge_NO_Shorted#1 -16.225,29.06 r180 top
SB15 "Solderbridge" Solderbridge_NO_Shorted#1 -29.32,8.975 r270 top
SB16 "Solderbridge" Solderbridge_NO_Shorted#1 -31.076,21.066 r90 top
SB17 "Solderbridge_Shorted" Solderbridge_Shorted#1 -18.225,29.06 r180 top net-tie
SB18 "Solderbridge_Shorted" Solderbridge_Shorted#1 -29.422,31.067 r0 top net-tie
SB19 "Solderbridge_Shorted" Solderbridge_Shorted#1 -29.397,32.655 r0 top net-tie
SB20 "Solderbridge_Shorted" Solderbridge_Shorted#1 -20.225,29.16 r180 top net-tie
SB21 "Solderbridge_Shorted" Solderbridge_Shorted#1 -20.225,30.96 r180 top net-tie
SB22 "Solderbridge_Shorted" Solderbridge_Shorted#1 -29.269,29.493 r0 top net-tie
TP1 "Testpoint" test#1 -9.598,16.877 r90 top
TP2 "Testpoint" test#2 -9.598,15.41 r90 top
TP3 "Testpoint" test#3 -16.225,27.36 r90 top
TP4 "Testpoint" test#3 -18.225,27.36 r90 top
TP5 "Testpoint" test#3 -31.076,26.401 r90 top
TP6 "Testpoint" test#3 -26.763,20.973 r90 bottom
TP7 "Testpoint" test#3 -26.307,9.214 r90 top
TP8 "Testpoint" test#3 -7.566,15.712 r90 top
TP9 "Testpoint" test#3 -5.534,15.712 r90 top
TP10 "Testpoint" test#3 -27.909,10.788 r180 bottom
TP11 "Testpoint" test#3 -28.73,8.455 r180 bottom
TP12 "Testpoint" test#1 -19.875,10.38 r90 top
TP13 "Testpoint" test#1 -21.907,10.38 r90 top
TP14 "Testpoint" test#3 -3.502,15.712 r90 top
TP15 "Testpoint" test#4 -1.597,15.788 r90 top
TP16 "Testpoint" test#1 -5.633,5 r90 top
TP17 "Testpoint" test#3 -41.49,14.767 r90 bottom
TP18 "Testpoint" test#3 -53.122,11.185 r90 bottom
TP19 "Testpoint" test#3 -39.961,13.324 r90 bottom
TP20 "Testpoint" test#3 -38.016,12.811 r90 bottom
U1 "USBLC6-2SC6" SOT-23-6P -58.392,17.556 r180 top
U2 "USBLC6-2SC6" SOT-23-6P -40.62,9.102 r180 top locked
U3 "nPM1300-QEAAC0" QFN32(0.5)-5X5 -37.818,21.328 r180 bottom locked
U4 "SGM61020XKB6G" SOT-563-6 -33.418,6.661 r90 top locked
U5 "nRF5340-CLAA" BGA95C35P12X11_437X397X50 -48.975,20.712 r180 top locked
U6 "nRF54L15-QFAAC00" nRF54L15_QFN48_6X6_0.4 -21.187,26.837 r0 bottom locked
U7 "MX25R6435F" WSON8L_6X5_1.27 -24.839,30.04 r180 top
U8 "FSA2466UMX" FSA2466UMX_1.8x2.6_0.4 -45.947,24.75 r0 top locked
U9 "FSA2466UMX" FSA2466UMX_1.8x2.6_0.4 -35.538,15.509 r180 top locked
U10 "FSA2466UMX" FSA2466UMX_1.8x2.6_0.4 -53.079,24.75 r0 top
U11 "nRF93M1" nRF93M1 -20.807,18.479 r180 top locked
U12 "NSQA6V8AW5T2G" SOT-323-5 -51.359,16.867 r270 bottom
U13 "MFF2" MFF2 -22.651,15.842 r90 bottom
X1 "32MHz" 2016 -44.442,17.95 r270 top
X2 "32MHz" 2016 -16.175,22.553 r180 bottom

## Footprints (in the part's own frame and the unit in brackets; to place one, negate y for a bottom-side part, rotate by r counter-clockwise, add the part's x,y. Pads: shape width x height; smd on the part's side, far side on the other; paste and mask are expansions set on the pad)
0201_0.25D [mm]
  rect 0.3x0.3 smd mask+0.051: 1(-0.275,0) 2(0.275,0)
  body extent -0.3,-0.15 0.3,0.15, height 0.28
0201C_0.2D(NB) [mm]
  rrect17% 0.3x0.3 smd mask+0.05: 1(-0.25,0) 2(0.25,0)
  body extent -0.3,-0.15 0.3,0.15, height 0.3
0201L_0.2D(NB) [mm]
  rrect17% 0.3x0.3 smd mask+0.05: 1(-0.25,0) 2(0.25,0)
  body extent -0.3,-0.15 0.3,0.15, height 0.3
0402C_0.4D [mm]
  rect 0.525x0.6 smd: 1(-0.463,0) 2(0.463,0)
  body extent -0.5,-0.25 0.5,0.25, height 0.48
0402C_0.4D-NB [mm]
  rrect44% 0.45x0.5 smd mask+0.05: 1(-0.4,0) 2(0.4,0)
  body extent -0.5,-0.25 0.5,0.25, height 0.5
0402R_0.4D [mm]
  rect 0.525x0.6 smd: 1(-0.463,0) 2(0.463,0)
  body extent -0.5,-0.25 0.5,0.25, height 0.36
0603C_0.6D#1 [mm]
  rrect30% 0.8x0.9 smd mask+0.076: 1(-0.7,0) 2(0.7,0)
  body extent -0.8,-0.4 0.8,0.4, height 0.3
0603C_0.6D#2 [mm]
  rect 0.8x0.9 smd mask+0.076: 1(-0.7,0) 2(0.7,0)
  body extent -0.8,-0.4 0.8,0.4, height 0.3
0603C_0.6D(RF) [mm]
  rrect30% 0.7x0.9 smd mask+0.076: 1(-0.65,0) 2(0.65,0)
  body extent -0.8,-0.4 0.8,0.4, height 0.3
0603L_0.6D [mm]
  rrect30% 0.8x0.9 smd: 1(-0.712,0) 2(0.712,0)
  Top Layer pour cut-out: -0.312,-0.55 -0.312,0.55 0.31,0.55 0.31,-0.55
  body extent -0.8,-0.4 0.8,0.4, height 0.95
0603R_0.6D [mm]
  rect 0.8x0.9 smd: 1(-0.7,0) 2(0.7,0)
  body extent -0.8,-0.4 0.8,0.4, height 0.46
0805L_0.7D-NB [mm]
  rrect14% 0.7x1.4 smd mask+0.05: 1(-0.7,0) 2(0.7,0)
  body extent -1,-0.75 1,0.75, height 1.8
1206C_1.2D [mm]
  rect 1.6x1.8 smd: 1(-1.4,0) 2(1.4,0)
  body extent -1.6,-0.8 1.6,0.8, height 1
2016 [mm]
  rect 0.9x0.8 smd: 1(-0.725,-0.575) 2(0.725,-0.575) 3(0.725,0.575) 4(-0.725,0.575)
  rect 0.65x0.55 on Mech16: ""(-0.675,0.525) ""(-0.675,-0.525) ""(0.675,0.525) ""(0.675,-0.525)
  round 0.2 on Mech16: ""(0,0) ""(0,0)
  body extent -1.05,-0.85 1.05,0.85, height 0.56
ANT_PCB [mm]
  rect 0.45x0.3 smd paste-2.54 mask+0.05: 1(0,0)
  rect 0.9x0.3 smd paste-2.54 mask+0.05: 2(1.555,0)
  Top Layer region: -9.625,2.65 -7.925,2.65 -7.925,3.6 -6.375,3.6 -6.375,2.65 -5.725,2.65 -5.725,3.6 -4.175,3.6 -4.175,2.65 -3.525,2.65 -3.525,3.6 -1.975,3.6 -1.975,2.65 -1.325,2.65 -1.325,3.6 0.225,3.6 0.225,3.3 2.005,3.3 2.005,-0.15 1.105,-0.15 1.105,2.85 0.225,2.85 0.225,-0.15 -0.225,-0.15 -0.225,3.15 -0.875,3.15 -0.875,2.2 -2.425,2.2 -2.425,3.15 -3.075,3.15 -3.075,2.2 -4.625,2.2 -4.625,3.15 -5.275,3.15 -5.275,2.2 -6.825,2.2 -6.825,3.15 -7.475,3.15 -7.475,2.2 -10.075,2.2 -10.075,5.1 1.925,5.1 1.925,4.65 -9.625,4.65
BGA95C35P12X11_437X397X50 [mm] "BGA, 95-Leads, Body 4.37x3.97mmx0.50mm, Pitch 0.35mm"
  round 0.17 smd mask+0.05: A1(-1.925,1.75) A2(-1.575,1.75) A3(-1.225,1.75) A5(-0.525,1.75) A7(0.175,1.75) A9(0.875,1.75) A11(1.575,1.75) A12(1.925,1.75) B1(-1.925,1.4) B2(-1.575,1.4) B4(-0.875,1.4) B5(-0.525,1.4) B6(-0.175,1.4) B7(0.175,1.4) B8(0.525,1.4) B9(0.875,1.4) B10(1.225,1.4) B11(1.575,1.4) B12(1.925,1.4) C2(-1.575,1.05) C4(-0.875,1.05) C5(-0.525,1.05) C6(-0.175,1.05) C7(0.175,1.05) C8(0.525,1.05) C9(0.875,1.05) C10(1.225,1.05) C11(1.575,1.05) D1(-1.925,0.7) D2(-1.575,0.7) D10(1.225,0.7) D11(1.575,0.7) D12(1.925,0.7) E2(-1.575,0.35) E3(-1.225,0.35) E4(-0.875,0.35) E5(-0.525,0.35) E6(-0.175,0.35) E7(0.175,0.35) E8(0.525,0.35) E10(1.225,0.35) E11(1.575,0.35) F1(-1.925,0) F2(-1.575,0) F3(-1.225,0) F5(-0.525,0) F6(-0.175,0) F7(0.175,0) F8(0.525,0) F10(1.225,0) F11(1.575,0) F12(1.925,0) G2(-1.575,-0.35) G3(-1.225,-0.35) G5(-0.525,-0.35) G6(-0.175,-0.35) G7(0.175,-0.35) G8(0.525,-0.35) G10(1.225,-0.35) G11(1.575,-0.35) H1(-1.925,-0.7) H2(-1.575,-0.7) H3(-1.225,-0.7) H10(1.225,-0.7) H11(1.575,-0.7) H12(1.925,-0.7) J2(-1.575,-1.05) J3(-1.225,-1.05) J4(-0.875,-1.05) J5(-0.525,-1.05) J6(-0.175,-1.05) J7(0.175,-1.05) J8(0.525,-1.05) J9(0.875,-1.05) J10(1.225,-1.05) J11(1.575,-1.05) K1(-1.925,-1.4) K2(-1.575,-1.4) K3(-1.225,-1.4) K4(-0.875,-1.4) K5(-0.525,-1.4) K6(-0.175,-1.4) K7(0.175,-1.4) K8(0.525,-1.4) K9(0.875,-1.4) K10(1.225,-1.4) K11(1.575,-1.4) K12(1.925,-1.4) L1(-1.925,-1.75) L3(-1.225,-1.75) L5(-0.525,-1.75) L7(0.175,-1.75) L9(0.875,-1.75) L11(1.575,-1.75) L12(1.925,-1.75)
  silkscreen extent -2.38,2.21 -2.28,2.31, body extent -2.13,-1.93 2.26,2.06, height 0.41
CON1 [mm]
  rect 1.2x2 smd: 0(-2.3,-1.725) 0(2.3,-1.725)
  rect 0.5x1.55 smd: 1(-1,2.05) 2(0,2.05) 3(1,2.05)
  silkscreen extent -1.72,2.73 -1.53,2.91, body extent -2.75,-2.5 2.75,2.5, height 3.4
D0201-NP [mm]
  rect 0.3x0.35 smd mask+0.051: A(0.25,0) K(-0.25,0)
  rect 0.2x0.3 on Mech16: ""(-0.2,0) ""(0.2,0)
  body extent -0.33,-0.18 0.33,0.18, height 0.34
D0402 [mm]
  rect 0.6x0.7 smd: A(0.55,0) K(-0.55,0)
  body extent -0.55,-0.33 0.55,0.33, height 0.56
D1616-RGB [mm]
  rect 0.55x0.4 smd mask+0.051: A1(0.625,0.725) A3(0.625,-0.725) K1(-0.625,0.725) K3(-0.625,-0.725)
  rect 0.75x0.5 smd mask+0.051: A2(0.725,0) K2(-0.725,0)
  rect 0.4x0.35 on Mech16: ""(-0.6,0.625) ""(-0.6,-0.625) ""(0.6,0.625) ""(0.6,-0.625)
  rect 0.4x0.6 on Mech16: ""(-0.6,0) ""(0.6,0)
  round 0.3 on Mech16: ""(0,0)
DFN1006 [mm]
  rect 0.4x0.7 smd mask+0.051: A(0.35,0) K(-0.35,0)
  rect 0.25x0.5 on Mech16: ""(-0.325,0) ""(0.325,0)
  body extent -0.5,-0.3 0.5,0.3, height 0.5
FSA2466UMX_1.8x2.6_0.4 [mm]
  rect 0.663x0.22 smd mask+0.051: 1(-0.718,0.6)
  rect 0.563x0.22 smd mask+0.051: 2(-0.768,0.2) 3(-0.768,-0.2) 4(-0.768,-0.6) 9(0.769,-0.6) 10(0.769,-0.2) 11(0.769,0.2) 12(0.769,0.6)
  rect 0.22x0.563 smd mask+0.051: 5(-0.6,-1.168) 6(-0.2,-1.169) 7(0.2,-1.168) 8(0.6,-1.169) 13(0.6,1.169) 14(0.2,1.168) 15(-0.2,1.168) 16(-0.6,1.168)
  silkscreen extent -1.15,0.86 -1.04,0.97, body extent -0.9,-1.3 0.9,1.3, height 0.6
L-0.85X0.65 [mm]
  rect 0.3x0.3 smd mask+0.051: 1(-0.25,0.3) 2(0.25,0.3) 3(0.25,-0.3) 4(-0.25,-0.3)
  body extent -0.43,-0.33 0.43,0.32, height 0.45
logo [mm]
MFF2 [mm]
  rect 3.9x3.3 smd mask+0.102: 0(0,0)
  rect 0.6x1.2 smd mask+0.102: 1(-1.905,-2.9) 2(-0.635,-2.9) 3(0.635,-2.9) 4(1.905,-2.9) 5(1.905,2.9) 6(0.635,2.9) 7(-0.635,2.9) 8(-1.905,2.9)
  rect 4.45x4.2 on Mech16 paste-2: 8(0,0)
  rect 3.9x3.3 on Mech16 paste-2: 9(0,0)
nRF54L15_QFN48_6X6_0.4 [mm]
  rect 0.8x0.2 smd mask+0.051: 1(-2.98,2.2)
  oval 0.8x0.2 smd mask+0.051: 2(-2.98,1.8) 3(-2.98,1.4) 4(-2.98,1) 5(-2.98,0.6) 6(-2.98,0.2) 7(-2.98,-0.2) 8(-2.98,-0.6) 9(-2.98,-1) 10(-2.98,-1.4) 11(-2.98,-1.8) 12(-2.98,-2.2) 25(2.98,-2.2) 26(2.98,-1.8) 27(2.98,-1.4) 28(2.98,-1) 29(2.98,-0.6) 30(2.98,-0.2) 31(2.98,0.2) 32(2.98,0.6) 33(2.98,1) 34(2.98,1.4) 35(2.98,1.8) 36(2.98,2.2)
  oval 0.2x0.8 smd mask+0.051: 13(-2.2,-2.98) 14(-1.8,-2.98) 15(-1.4,-2.98) 16(-1,-2.98) 17(-0.6,-2.98) 18(-0.2,-2.98) 19(0.2,-2.98) 20(0.6,-2.98) 21(1,-2.98) 22(1.4,-2.98) 23(1.8,-2.98) 24(2.2,-2.98) 37(2.2,2.98) 38(1.8,2.98) 39(1.4,2.98) 40(1,2.98) 41(0.6,2.98) 42(0.2,2.98) 43(-0.2,2.98) 44(-0.6,2.98) 45(-1,2.98) 46(-1.4,2.98) 47(-1.8,2.98) 48(-2.2,2.98)
  rrect50% 1.2x1.2 smd: 49(-1.55,-1.55) 49(-1.55,0) 49(-1.55,1.55) 49(0,-1.55) 49(0,0) 49(0,1.55) 49(1.55,-1.55) 49(1.55,0) 49(1.55,1.55)
  rrect50% 0.2x1.5 smd rot 135: 49(-0.8,-0.8) 49(0.8,0.8)
  rrect50% 0.2x1.5 smd rot 45: 49(-0.8,0.8) 49(0.8,-0.8)
  rrect50% 1.1x0.3 smd: 49(-0.725,0) 49(0.7,0)
  rrect50% 0.3x1.1 smd: 49(0,0.775) 49(0,-0.6)
  rect 4.6x4.6 on Mech16: ""(0,0)
  silkscreen extent -3,2.72 -2.72,3, body extent -3,-3 3,3, height 1
nRF93M1 [mm]
  round 1 on Mech16: 0(0,0)
  rrect20% 0.6x1.2 smd mask+0.076: 1(-6.6,-7.15) 2(-5.5,-7.15) 3(-4.4,-7.15) 4(-3.3,-7.15) 5(-2.2,-7.15) 6(-1.1,-7.15) 7(0,-7.15) 8(1.1,-7.15) 9(2.2,-7.15) 10(3.3,-7.15) 11(4.4,-7.15) 12(5.5,-7.15) 13(6.6,-7.15) 23(6.6,7.15) 24(5.5,7.15) 25(4.4,7.15) 26(3.3,7.15) 27(2.2,7.15) 28(1.1,7.15) 29(0,7.15) 30(-1.1,7.15) 31(-2.2,7.15) 32(-3.3,7.15) 33(-4.4,7.15) 34(-5.5,7.15) 35(-6.6,7.15)
  rrect20% 1.2x0.6 smd mask+0.076: 14(8.1,-4.4) 15(8.1,-3.3) 16(8.1,-2.2) 17(8.1,-1.1) 18(8.1,0) 19(8.1,1.1) 20(8.1,2.2) 21(8.1,3.3) 22(8.1,4.4) 36(-8.1,4.4) 37(-8.1,3.3) 38(-8.1,2.2) 39(-8.1,1.1) 40(-8.1,0) 41(-8.1,-1.1) 42(-8.1,-2.2) 43(-8.1,-3.3) 44(-8.1,-4.4) 95(8.1,-5.5) 96(8.1,5.5) 97(-8.1,5.5) 98(-8.1,-5.5)
  rrect30% 0.7x1 smd mask+0.064: 45(-4.8,-5) 46(-3.6,-5) 47(-2.4,-5) 48(-1.2,-5) 49(0,-5) 50(1.2,-5) 51(2.4,-5) 52(3.6,-5) 53(4.8,-5) 59(4.8,5) 60(3.6,5) 61(2.4,5) 62(1.2,5) 63(0,5) 64(-1.2,5) 65(-2.4,5) 66(-3.6,5) 67(-4.8,5) 73(-4.2,-3.2) 74(-3,-3.2) 75(-1.8,-3.2) 76(-0.6,-3.2) 77(0.6,-3.2) 78(1.8,-3.2) 79(3,-3.2) 80(4.2,-3.2) 81(4.2,3.2) 82(3,3.2) 83(1.8,3.2) 84(0.6,3.2) 85(-0.6,3.2) 86(-1.8,3.2) 87(-3,3.2) 88(-4.2,3.2) 99(-6,-5) 100(6,-5) 103(6,5) 104(-6,5)
  rrect30% 1x0.7 smd mask+0.064: 54(5.95,-2.4) 55(5.95,-1.2) 56(5.95,0) 57(5.95,1.2) 58(5.95,2.4) 68(-5.95,2.4) 69(-5.95,1.2) 70(-5.95,0) 71(-5.95,-1.2) 72(-5.95,-2.4) 101(5.95,-3.6) 102(5.95,3.6) 105(-5.95,3.6) 106(-5.95,-3.6) 107(4.2,-1.2) 108(4.2,0) 109(4.2,1.2)
  rrect20% 1.3x1.3 smd mask+0.064: 89(-1.8,-0.9) 90(0,-0.9) 91(1.8,-0.9) 92(1.8,0.9) 93(0,0.9) 94(-1.8,0.9)
  silkscreen extent -9,-8.53 9,8.05
QFN32(0.5)-5X5 [mm]
  rrect50% 1.4x1.4 smd: 0(-1,-1) 0(-1,1) 0(1,-1) 0(1,1)
  rrect50% 1.6x1.6 smd: 0(0,0)
  rect 0.8x0.28 smd mask+0.051: 1(-2.5,1.75)
  oval 0.8x0.28 smd mask+0.051: 2(-2.5,1.25) 3(-2.5,0.75) 4(-2.5,0.25) 5(-2.5,-0.25) 6(-2.5,-0.75) 7(-2.5,-1.25) 8(-2.5,-1.75) 17(2.5,-1.75) 18(2.5,-1.25) 19(2.5,-0.75) 20(2.5,-0.25) 21(2.5,0.25) 22(2.5,0.75) 23(2.5,1.25) 24(2.5,1.75)
  oval 0.28x0.8 smd mask+0.051: 9(-1.75,-2.5) 10(-1.25,-2.5) 11(-0.75,-2.5) 12(-0.25,-2.5) 13(0.25,-2.5) 14(0.75,-2.5) 15(1.25,-2.5) 16(1.75,-2.5) 25(1.75,2.5) 26(1.25,2.5) 27(0.75,2.5) 28(0.25,2.5) 29(-0.25,2.5) 30(-0.75,2.5) 31(-1.25,2.5) 32(-1.75,2.5)
  round 0.4 on Mech15: ""(-2.5,1.75)
  rect 3.5x3.5 on Mech16: ""(0,0)
  silkscreen extent -3.42,1.44 -3.1,2.07, body extent -2.5,-2.5 2.5,2.5, height 1.05
SIM-MUP-C7801 [mm]
  rect 0.58x2.1 smd: 0(-6.5,5.258) 0(-6.5,-6.742) 0(6.5,-6.742) 0(6.5,5.258)
  rect 1.8x2.8 on Mech16: 0(-3.82,-5.743) 0(-1.28,-5.743) 0(1.26,-5.743)
  rect 1.4x2.95 on Mech16: 0(-3.82,0.233) 0(-1.28,0.233) 0(1.26,0.233)
  rect 1.4x2.3 on Mech16: 0(1.26,4.257)
  rect 0.7x1.13 smd: 1(0.25,6.743) 2(-2.29,6.743) 5(1.52,6.743) 6(-1.02,6.743) 7(-3.56,6.743)
  rect 0.75x1.13 smd: 3(-4.83,6.743)
  rect 0.65x1.13 smd: CD(2.47,6.743)
  silkscreen extent -6.1,-7.79 6.1,6.01, body extent -6.54,-7.75 6.55,6.8, height 1.5
"SIP 2.54_3_S"#1 [mm]
  oval 1.4x1.7 hole 1.02: 1(0,0) 2(0,-2.54) 3(0,-5.08)
"SIP 2.54_3_S"#2 [mm]
  oval 1.4x1.7 hole 1.02: 1(0,0)
  oval 1.45x1.7 hole 1.02: 2(0,-2.54) 3(0,-5.08)
"SIP 2.54_4_S" [mm]
  oval 1.4x1.6 hole 1.02: 1(0,0) 2(0,-2.54) 3(0,-5.08) 4(0,-7.62)
  body extent -1.27,-8.89 1.27,1.27, height 10.3
"SIP 2.54_5_S" [mm]
  oval 1.45x1.7 hole 1.02: 1(0,0) 2(0,-2.54) 3(0,-5.08) 4(0,-7.62) 5(0,-10.16)
  body extent -1.27,-11.43 1.27,1.27, height 10.3
"SIP 2.54_7_S" [mm]
  oval 1.4x1.7 hole 1.02: 1(0,0) 2(0,-2.54) 3(0,-5.08) 4(0,-7.62) 5(0,-10.16) 6(0,-12.7) 7(0,-15.24)
  body extent -1.27,-16.51 1.27,1.27, height 10.3
SKFB160808-2R2M#1 [mm]
  rect 0.65x0.95 smd mask+0.076: 1(-0.6,0) 2(0.6,0)
  body extent -0.8,-0.4 0.8,0.4, height 0.8
SKFB160808-2R2M#2 [mm]
  rrect30% 0.65x0.95 smd mask+0.076: 1(-0.6,0) 2(0.6,0)
  body extent -0.8,-0.4 0.8,0.4, height 0.8
SMA-SMD [mm]
  rect 1.2x4 smd paste-4: 1(0,0)
  rect 1.8x4 smd paste-4: 2(-2.5,0) 2(2.5,0)
  rect 1.8x4 smd far side paste-4: 2(-2.5,0) 2(2.5,0)
  body extent -3.07,-1.75 3.02,11.75, height 3.5
SOD-523-NP [mm]
  rect 0.6x0.4 smd: A(0.75,0) K(-0.75,0)
  body extent -0.8,-0.4 0.8,0.4, height 0.7
Solderbridge_NO_Shorted#1 [mil]
  round 1 smd paste-99999: 1(-13.78,0) 2(13.78,0)
  Top Layer region: -7.49,19.36 -9.17,19.05 -12.39,17.86 -15.35,16.13 -17.96,13.92 -20.16,11.29 -21.86,8.31 -23.03,5.09 -23.62,1.71 -23.62,0 -23.62,-1.71 -23.03,-5.09 -21.86,-8.31 -20.16,-11.29 -17.96,-13.92 -15.35,-16.13 -12.39,-17.86 -9.17,-19.05 -7.49,-19.36 -6.83,-19.48 -5.53,-19.14 -4.51,-18.29 -3.94,-17.07 -3.94,-16.4 -3.94,-16.4 -3.94,16.4 -3.94,17.07 -4.5,18.29 -5.53,19.14 -6.83,19.48 -7.49,19.36
  Top Layer region: 7.49,-19.36 9.17,-19.05 12.39,-17.86 15.35,-16.13 17.96,-13.92 20.16,-11.29 21.86,-8.31 23.03,-5.09 23.62,-1.71 23.62,0 23.62,1.71 23.03,5.09 21.86,8.31 20.16,11.29 17.96,13.92 15.35,16.13 12.39,17.86 9.17,19.05 7.49,19.36 6.83,19.48 5.53,19.14 4.51,18.29 3.94,17.07 3.94,16.4 3.94,16.4 3.94,-16.4 3.94,-17.07 4.5,-18.29 5.53,-19.14 6.83,-19.48 7.49,-19.36
Solderbridge_NO_Shorted#2 [mil]
  round 1 smd paste+0: 1(-13.78,0) 2(13.78,0)
  Top Layer region: -7.49,19.36 -9.17,19.05 -12.39,17.86 -15.35,16.13 -17.96,13.92 -20.16,11.29 -21.86,8.31 -23.03,5.09 -23.62,1.71 -23.62,0 -23.62,-1.71 -23.03,-5.09 -21.86,-8.31 -20.16,-11.29 -17.96,-13.92 -15.35,-16.13 -12.39,-17.86 -9.17,-19.05 -7.49,-19.36 -6.83,-19.48 -5.53,-19.14 -4.51,-18.29 -3.94,-17.07 -3.94,-16.4 -3.94,-16.4 -3.94,16.4 -3.94,17.07 -4.5,18.29 -5.53,19.14 -6.83,19.48 -7.49,19.36
  Top Layer region: 7.49,-19.36 9.17,-19.05 12.39,-17.86 15.35,-16.13 17.96,-13.92 20.16,-11.29 21.86,-8.31 23.03,-5.09 23.62,-1.71 23.62,0 23.62,1.71 23.03,5.09 21.86,8.31 20.16,11.29 17.96,13.92 15.35,16.13 12.39,17.86 9.17,19.05 7.49,19.36 6.83,19.48 5.53,19.14 4.51,18.29 3.94,17.07 3.94,16.4 3.94,16.4 3.94,-16.4 3.94,-17.07 4.5,-18.29 5.53,-19.14 6.83,-19.48 7.49,-19.36
Solderbridge_Shorted#1 [mil]
  round 1 smd paste-99999: 1(-13.78,0) 2(13.78,0)
  Top Layer region: -7.49,19.36 -9.17,19.05 -12.39,17.86 -15.35,16.13 -17.96,13.92 -20.16,11.29 -21.86,8.31 -23.03,5.09 -23.62,1.71 -23.62,0 -23.62,-1.71 -23.03,-5.09 -21.86,-8.31 -20.16,-11.29 -17.96,-13.92 -15.35,-16.13 -12.39,-17.86 -9.17,-19.05 -7.49,-19.36 -6.83,-19.48 -5.53,-19.14 -4.5,-18.29 -3.94,-17.07 -3.94,-16.4 -3.94,-16.4 -3.94,16.4 -3.94,17.07 -4.5,18.29 -5.53,19.14 -6.83,19.48 -7.49,19.36
  Top Layer region: 7.49,-19.36 9.17,-19.05 12.39,-17.86 15.35,-16.13 17.96,-13.92 20.16,-11.29 21.86,-8.31 23.03,-5.09 23.62,-1.71 23.62,0 23.62,1.71 23.03,5.09 21.86,8.31 20.16,11.28 17.96,13.92 15.35,16.13 12.39,17.86 9.17,19.05 7.49,19.36 6.83,19.48 5.53,19.14 4.51,18.29 3.94,17.07 3.94,16.4 3.94,16.4 3.94,-16.4 3.94,-17.07 4.51,-18.29 5.53,-19.14 6.83,-19.48 7.49,-19.36
  Top Layer region: -4.92,3.94 -4.92,-3.94 4.92,-3.94 4.92,3.94
Solderbridge_Shorted#2 [mil]
  round 1 smd paste+0: 1(-13.78,0) 2(13.78,0)
  Top Layer region: -7.49,19.36 -9.17,19.05 -12.39,17.86 -15.35,16.13 -17.96,13.92 -20.16,11.29 -21.86,8.31 -23.03,5.09 -23.62,1.71 -23.62,0 -23.62,-1.71 -23.03,-5.09 -21.86,-8.31 -20.16,-11.29 -17.96,-13.92 -15.35,-16.13 -12.39,-17.86 -9.17,-19.05 -7.49,-19.36 -6.83,-19.48 -5.53,-19.14 -4.5,-18.29 -3.94,-17.07 -3.94,-16.4 -3.94,-16.4 -3.94,16.4 -3.94,17.07 -4.5,18.29 -5.53,19.14 -6.83,19.48 -7.49,19.36
  Top Layer region: 7.49,-19.36 9.17,-19.05 12.39,-17.86 15.35,-16.13 17.96,-13.92 20.16,-11.29 21.86,-8.31 23.03,-5.09 23.62,-1.71 23.62,0 23.62,1.71 23.03,5.09 21.86,8.31 20.16,11.28 17.96,13.92 15.35,16.13 12.39,17.86 9.17,19.05 7.49,19.36 6.83,19.48 5.53,19.14 4.51,18.29 3.94,17.07 3.94,16.4 3.94,16.4 3.94,-16.4 3.94,-17.07 4.51,-18.29 5.53,-19.14 6.83,-19.48 7.49,-19.36
  Top Layer region: -4.92,3.94 -4.92,-3.94 4.92,-3.94 4.92,3.94
SOT-23-6P [mm]
  rect 0.9x0.5 smd: 1(1.25,-0.95)
  oval 0.9x0.5 smd: 2(1.25,0) 3(1.25,0.95) 4(-1.25,0.95) 5(-1.25,0) 6(-1.25,-0.95)
  silkscreen extent 2.06,-1.19 2.34,-0.67, body extent -1.4,-1.45 1.4,1.45, height 1.45
SOT-323-3A [mm]
  rect 0.6x0.5 smd: B(0.925,-0.65) C(-0.925,0) E(0.925,0.65)
  rect 0.3x0.4 on Mech16: ""(-0.93,0) ""(0.93,0.65) ""(0.93,-0.65)
  round 0.15 on Mech16: ""(0,0) ""(0,0)
  body extent -1.08,-1 1.08,1, height 0.9
SOT-323-3G [mm]
  rect 0.6x0.5 smd: D(-0.925,0) G(0.925,-0.65) S(0.925,0.65)
  rect 0.3x0.4 on Mech16: ""(-0.93,0) ""(0.93,0.65) ""(0.93,-0.65)
  round 0.15 on Mech16: ""(0,0) ""(0,0)
  body extent -1.08,-1 1.08,1, height 0.9
SOT-323-5 [mm]
  rect 0.8x0.4 smd mask+0.051: 1(1,-0.65) 2(1,0) 3(1,0.65) 4(-1,0.65) 5(-1,-0.65)
  body extent -1.2,-1.1 1.2,1.1, height 1.1
SOT-563-6 [mm]
  rect 0.25x0.55 smd mask+0.05: 1(-0.5,-0.8) 2(0,-0.8) 3(0.5,-0.8) 5(0,0.8)
  rect 0.25x0.55 smd mask+0.051: 4(0.5,0.8) 6(-0.5,0.8)
  rect 0.22x0.25 on Mech16 paste+0 mask+0.102: ""(-0.5,-0.725) ""(-0.5,0.725) ""(0,-0.725) ""(0.5,0.725) ""(0.5,-0.725)
  silkscreen extent -0.75,-1.49 -0.27,-1.25, body extent -0.8,-0.81 0.8,0.81, height 0.59
SW-4.2X3.35-4P-S [mm]
  rect 1.3x0.8 smd paste+0: 1(-1.85,1.1) 2(1.85,1.1) 3(-1.85,-1.1) 4(1.85,-1.1)
  body extent -2.3,-1.68 2.3,1.68, height 2.5
TC2050-IDC-NLFP [mil]
  round 39 hole 39 unplated mask+0.79: 0(-150,0) 0(150,-40) 0(150,40)
  round 31 smd paste-196.85: 1(-100,-25) 2(-50,-25) 3(0,-25) 4(50,-25) 5(100,-25) 6(100,25) 7(50,25) 8(0,25) 9(-50,25) 10(-100,25)
  Top Layer pour cut-out: -100,25 -100,-25 100,-25 100,25
test#1 [mm]
  round 1 smd paste-10: 1(-1.166,0)
test#2 [mm]
  round 1 smd paste-10: 1(-1.73,0)
test#3 [mm]
  round 1 smd paste-10: 1(0,0)
test#4 [mm]
  round 1 smd paste-10: 1(-0.076,-0.127)
UDFN2(1610) [mm]
  rect 0.58x1 smd mask+0.076: A(0.56,0) K(-0.56,0)
  rect 0.4x0.88 on Mech16: ""(-0.55,0) ""(0.55,0)
  body extent -0.8,-0.5 0.8,0.5, height 0.59
USB-TYPEC-MUP-U20402-1#1 [mm]
  oval 1x1.8 hole 0.6 slot 1.4 at 90 deg: 0(-4.32,2.85) 0(4.32,2.85)
  oval 1x2.2 hole 0.6 slot 1.8 at 90 deg: 0(-4.32,-1.15)
  oval 0.85x2.2 hole 0.6 slot 1.8 at 90 deg: 0(4.32,-1.15)
  rect 0.3x1.15 smd mask+0.05: A1(-3.35,3.425) A4(-2.55,3.425) A5(-1.25,3.425) A6(-0.25,3.425) A7(0.25,3.425) A8(1.25,3.425) A9(2.55,3.425) A12(3.35,3.425) B1(3.05,3.425) B4(2.25,3.425) B5(1.75,3.425) B6(0.75,3.425) B7(-0.75,3.425) B8(-1.75,3.425) B9(-2.25,3.425) B12(-3.05,3.425)
USB-TYPEC-MUP-U20402-1#2 [mm]
  oval 1x2.2 hole 0.6 slot 1.8 at 90 deg: 0(-4.32,-1.15) 0(4.32,-1.15)
  oval 1x1.8 hole 0.6 slot 1.4 at 90 deg: 0(-4.32,2.85) 0(4.32,2.85)
  rect 0.3x1.15 smd mask+0.05: A1(-3.35,3.425) A4(-2.55,3.425) A5(-1.25,3.425) A6(-0.25,3.425) A7(0.25,3.425) A8(1.25,3.425) A9(2.55,3.425) A12(3.35,3.425) B1(3.05,3.425) B4(2.25,3.425) B5(1.75,3.425) B6(0.75,3.425) B7(-0.75,3.425) B8(-1.75,3.425) B9(-2.25,3.425) B12(-3.05,3.425)
WEEE_3x4.5mm [mm]
  silkscreen extent -1.47,-1.71 1.47,2.7
WSON8L_6X5_1.27 [mm]
  rect 1x0.55 smd mask+0.075: 1(-2.9,1.905) 2(-2.9,0.635) 3(-2.9,-0.635) 4(-2.9,-1.905) 5(2.9,-1.905) 6(2.9,-0.635) 7(2.9,0.635) 8(2.9,1.905)
  rect 3.4x4 smd mask+0.075: 9(0,0)
  rect 0.6x0.4 on Mech16 mask+0.075: ""(-2.7,-0.635) ""(-2.7,1.9) ""(-2.675,0.635) ""(-2.675,-1.9) ""(2.675,1.9) ""(2.675,-0.625) ""(2.675,0.65) ""(2.7,-1.9)
  body extent -3,-2.5 3,2.5, height 0.9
